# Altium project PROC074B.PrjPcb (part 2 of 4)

## Sheet PROC074B_LP_Connector.SchDoc
size 431 x 279 mm; Date: Not shown in title block; ApprovedBy: Not shown in title block; CheckedBy: Not shown in title block; Author: Not shown in title block; CompanyName: Not shown in title block; Engineer: Not shown in title block; Organization: Not shown in title block; Address1: Not shown in title block; Address2: Not shown in title block; Address3: Not shown in title block; Address4: Not shown in title block; DocumentNumber: 1; Revision: Use project parameter SCH_Rev; SheetNumber: 8; SheetTotal: 22; PageSetup: Record=PageOptions¦CenterHorizontal=True¦CenterVertical=True¦PrintScale=1.00¦XCorrection=1.00¦YCorrection=1.00¦PrintKind=0¦BorderSize=5000000¦LeftOffset=0¦BottomOffset=0¦Orientation=2¦PaperLength=1000¦PaperWidth=1000¦Scale=100¦PaperSource=15¦PrintQuality=600¦MediaType=1¦DitherType=10¦PaperKind=Letter¦PrintScaleMode=1
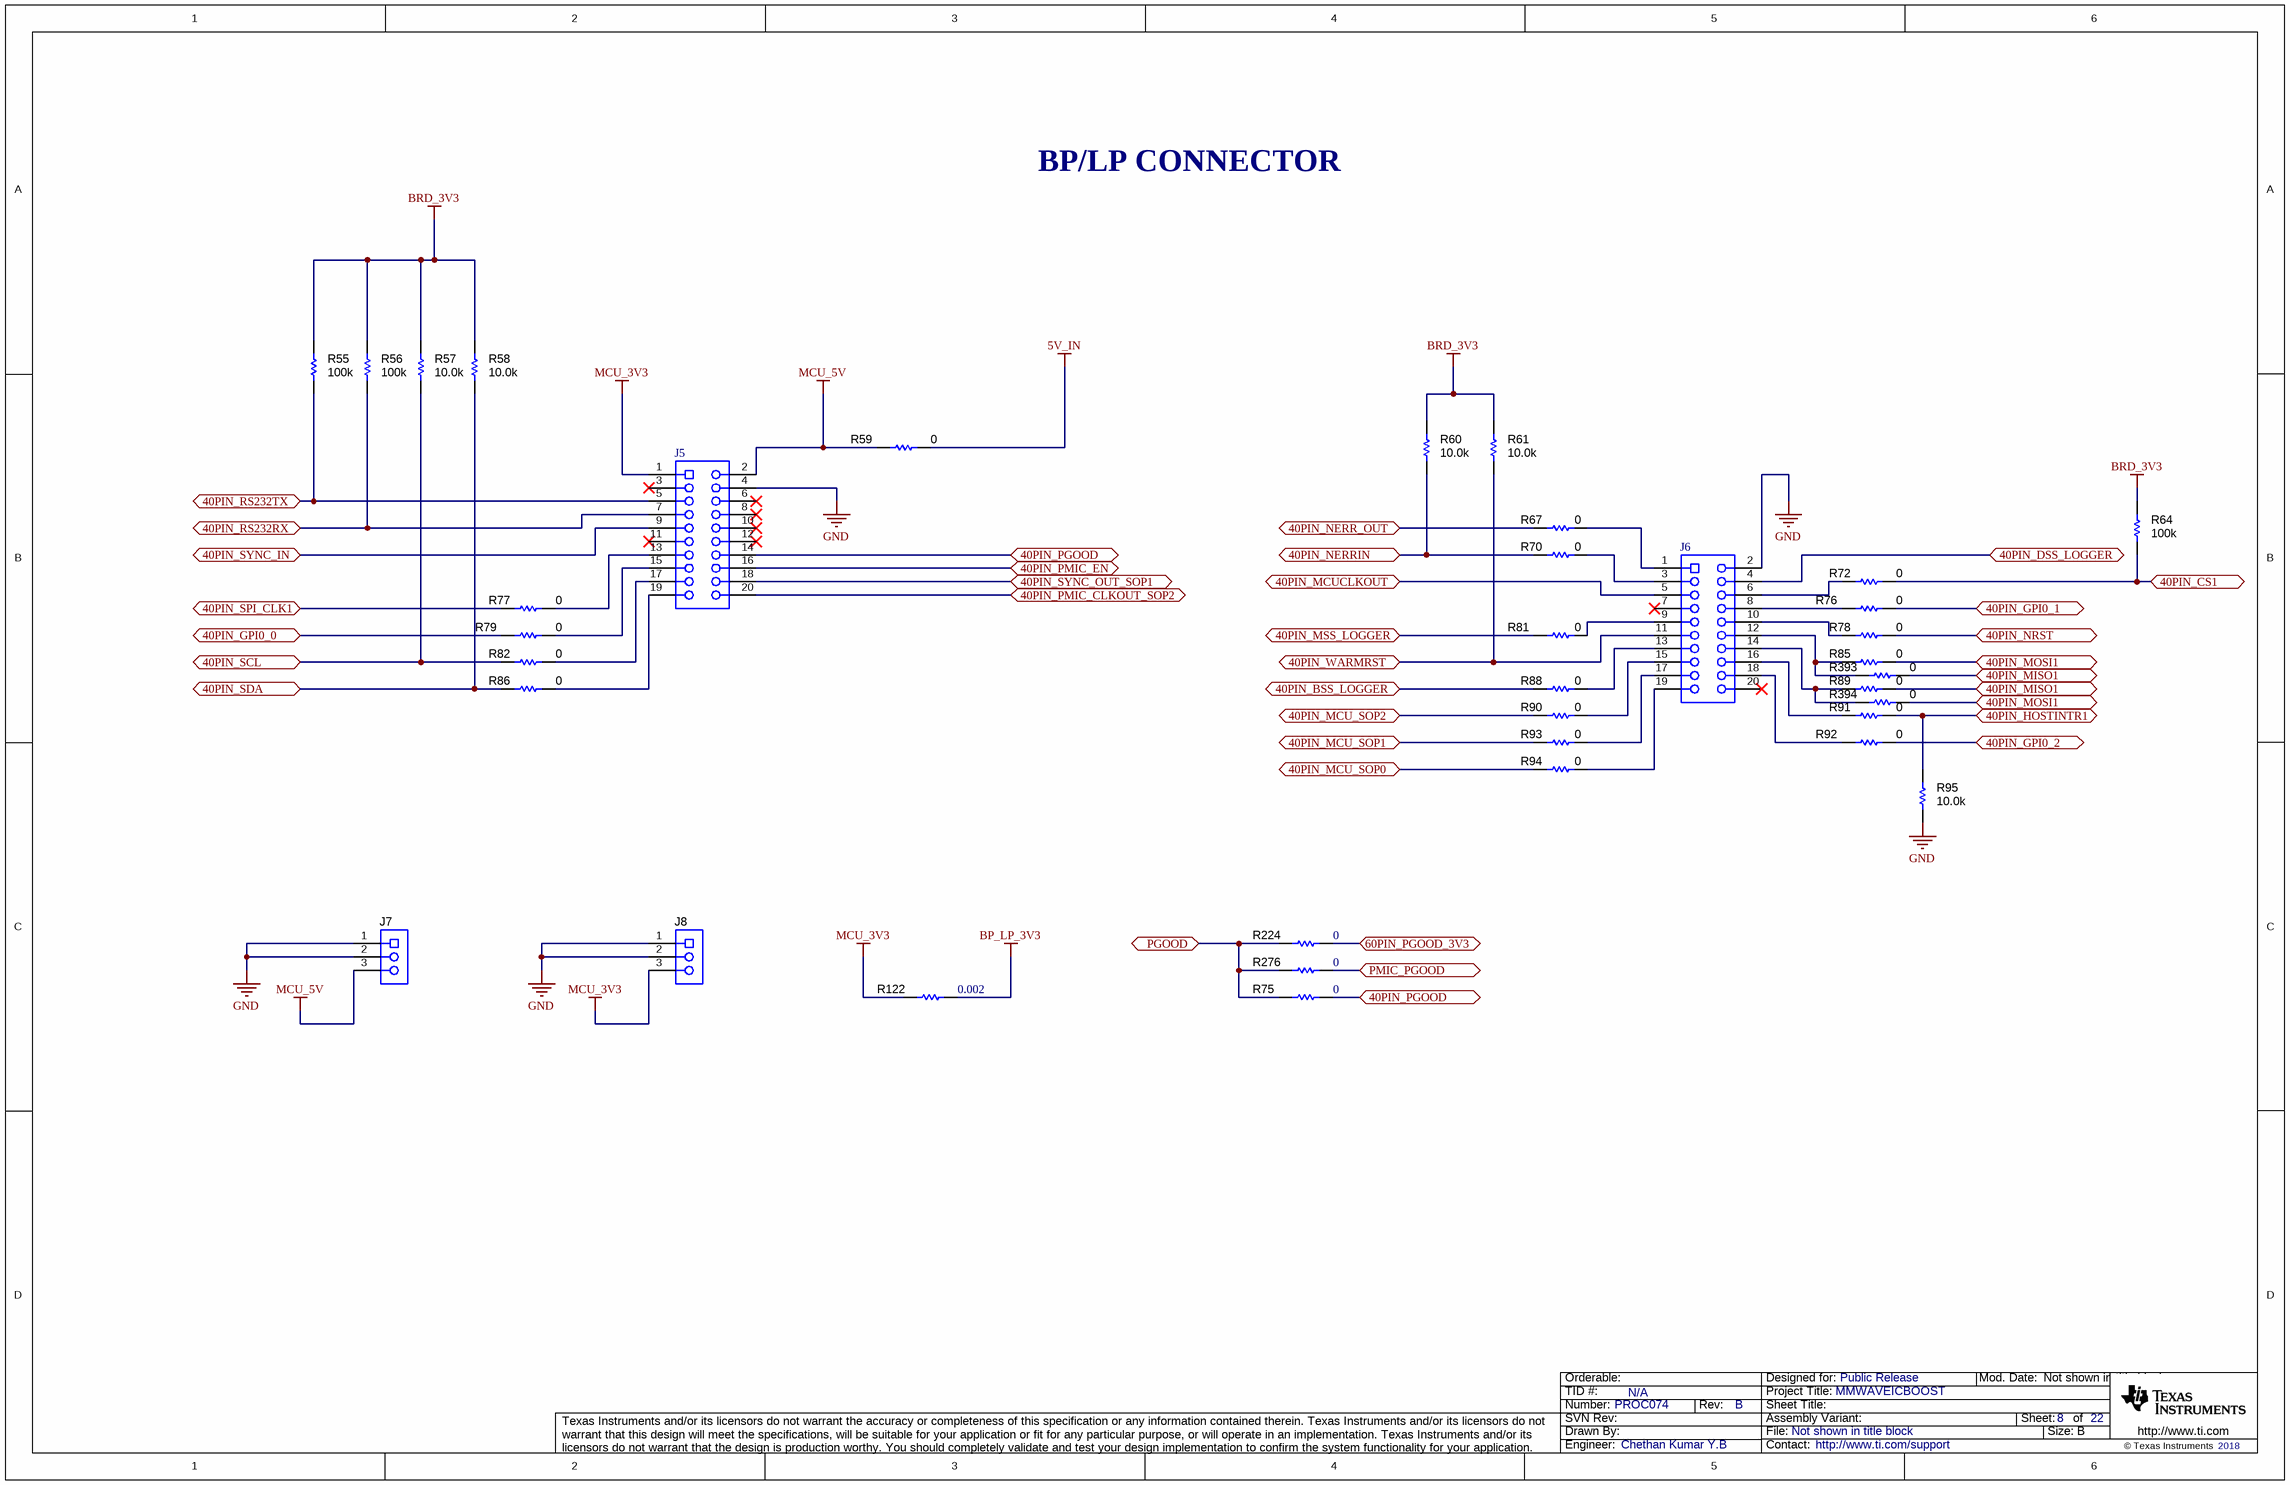
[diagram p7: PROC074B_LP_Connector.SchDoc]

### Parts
J5  SSM-110-S-DV  [Samtec_SSM-110-x-DV]  (value not drawn)
J6  SSM-110-S-DV  [Samtec_SSM-110-x-DV]  (value not drawn)
J7  SSM-103-S-SV  [Samtec_SSM-103-x-SV]  (value not drawn)
J8  SSM-103-S-SV  [Samtec_SSM-103-x-SV]  (value not drawn)
R55  ValueDisplayed: 100k  [0402L]  (hidden comment: CRCW0402100KFKED)
R56  ValueDisplayed: 100k  [0402L]  (hidden comment: CRCW0402100KFKED)
R57  ValueDisplayed: 10.0k  [0402L]  (hidden comment: CRCW040210K0FKED)
R58  ValueDisplayed: 10.0k  [0402L]  (hidden comment: CRCW040210K0FKED)
R59  ValueDisplayed: 0  [2010]  (hidden comment: CRCW20100000Z0EF)
R60  ValueDisplayed: 10.0k  [0402L]  (hidden comment: CRCW040210K0FKED)
R61  ValueDisplayed: 10.0k  [0402L]  (hidden comment: CRCW040210K0FKED)
R64  ValueDisplayed: 100k  [0402L]  (hidden comment: CRCW0402100KFKED)
R67  ValueDisplayed: 0  [0201_Silk]  (hidden comment: CRCW02010000Z0ED)
R70  ValueDisplayed: 0  [0201_Silk]  (hidden comment: CRCW02010000Z0ED)
R72  ValueDisplayed: 0  [0201_Silk]  (hidden comment: CRCW02010000Z0ED)
R75  ValueDisplayed: 0  [0402]  (hidden comment: ERJ-2GE0R00X)
R76  ValueDisplayed: 0  [0201_Silk]  (hidden comment: CRCW02010000Z0ED)
R77  ValueDisplayed: 0  [0201_Silk]  (hidden comment: CRCW02010000Z0ED)
R78  ValueDisplayed: 0  [0201_Silk]  (hidden comment: CRCW02010000Z0ED)
R79  ValueDisplayed: 0  [0201_Silk]  (hidden comment: CRCW02010000Z0ED)
R81  ValueDisplayed: 0  [0201_Silk]  (hidden comment: CRCW02010000Z0ED)
R82  ValueDisplayed: 0  [0201_Silk]  (hidden comment: CRCW02010000Z0ED)
R85  ValueDisplayed: 0  [0201_Silk]  (hidden comment: CRCW02010000Z0ED)
R86  ValueDisplayed: 0  [0201_Silk]  (hidden comment: CRCW02010000Z0ED)
R88  ValueDisplayed: 0  [0201_Silk]  (hidden comment: CRCW02010000Z0ED)
R89  ValueDisplayed: 0  [0201_Silk]  (hidden comment: CRCW02010000Z0ED)
R90  ValueDisplayed: 0  [0201_Silk]  (hidden comment: CRCW02010000Z0ED)
R91  ValueDisplayed: 0  [0201_Silk]  (hidden comment: CRCW02010000Z0ED)
R92  ValueDisplayed: 0  [0201_Silk]  (hidden comment: CRCW02010000Z0ED)
R93  ValueDisplayed: 0  [0201_Silk]  (hidden comment: CRCW02010000Z0ED)
R94  ValueDisplayed: 0  [0201_Silk]  (hidden comment: CRCW02010000Z0ED)
R95  ValueDisplayed: 10.0k  [0402L]  (hidden comment: CRCW040210K0FKED)
R122  ValueDisplayed: 0.002  [1206]  (hidden comment: PMR18EZPFV2L00)
R224  ValueDisplayed: 0  [0402]  (hidden comment: ERJ-2GE0R00X)
R276  ValueDisplayed: 0  [0402]  (hidden comment: ERJ-2GE0R00X)
R393  ValueDisplayed: 0  [0201_Silk]  (hidden comment: CRCW02010000Z0ED)
R394  ValueDisplayed: 0  [0201_Silk]  (hidden comment: CRCW02010000Z0ED)

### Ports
40PIN_BSS_LOGGER, 40PIN_CS1, 40PIN_DSS_LOGGER, 40PIN_GPI0_0, 40PIN_GPI0_1, 40PIN_GPI0_2, 40PIN_HOSTINTR1, 40PIN_MCU_SOP0, 40PIN_MCU_SOP1, 40PIN_MCU_SOP2, 40PIN_MCUCLKOUT, 40PIN_MISO1, 40PIN_MOSI1, 40PIN_MSS_LOGGER, 40PIN_NERR_OUT, 40PIN_NERRIN, 40PIN_NRST, 40PIN_PGOOD, 40PIN_PMIC_CLKOUT_SOP2, 40PIN_PMIC_EN, 40PIN_RS232RX, 40PIN_RS232TX, 40PIN_SCL, 40PIN_SDA, 40PIN_SPI_CLK1, 40PIN_SYNC_IN, 40PIN_SYNC_OUT_SOP1, 40PIN_WARMRST, 60PIN_PGOOD_3V3, PGOOD, PMIC_PGOOD

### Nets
5V_IN: R59.2
BP_LP_3V3: R122.2
BRD_3V3: R55.2 R56.2 R57.2 R58.2 R60.2 R61.2 R64.2
GND: J5.4 J6.2 J7.1 J7.2 J8.1 J8.2 R95.1
MCU_3V3: J5.1 J8.3 R122.1
MCU_5V: J5.2 J7.3 R59.1
40PIN_BSS_LOGGER: R88.1 ; port 40PIN_BSS_LOGGER
40PIN_CS1: R64.1 R72.2 ; port 40PIN_CS1
40PIN_DSS_LOGGER: J6.4 ; port 40PIN_DSS_LOGGER
40PIN_GPI0_0: R79.1 ; port 40PIN_GPI0_0
40PIN_GPI0_1: R76.2 ; port 40PIN_GPI0_1
40PIN_GPI0_2: R92.2 ; port 40PIN_GPI0_2
40PIN_HOSTINTR1: R91.2 R95.2 ; port 40PIN_HOSTINTR1
40PIN_MCU_SOP0: R94.1 ; port 40PIN_MCU_SOP0
40PIN_MCU_SOP1: R93.1 ; port 40PIN_MCU_SOP1
40PIN_MCU_SOP2: R90.1 ; port 40PIN_MCU_SOP2
40PIN_MCUCLKOUT: J6.5 ; port 40PIN_MCUCLKOUT
40PIN_MISO1: R89.2 R393.2 ; port 40PIN_MISO1
40PIN_MOSI1: R85.2 R394.2 ; port 40PIN_MOSI1
40PIN_MSS_LOGGER: R81.1 ; port 40PIN_MSS_LOGGER
40PIN_NERR_OUT: R67.1 ; port 40PIN_NERR_OUT
40PIN_NERRIN: R60.1 R70.1 ; port 40PIN_NERRIN
40PIN_NRST: R78.2 ; port 40PIN_NRST
40PIN_PGOOD: J5.14 R75.2 ; port 40PIN_PGOOD
40PIN_PMIC_CLKOUT_SOP2: J5.20 ; port 40PIN_PMIC_CLKOUT_SOP2
40PIN_PMIC_EN: J5.16 ; port 40PIN_PMIC_EN
40PIN_RS232RX: J5.7 R56.1 ; port 40PIN_RS232RX
40PIN_RS232TX: J5.5 R55.1 ; port 40PIN_RS232TX
40PIN_SCL: R57.1 R82.1 ; port 40PIN_SCL
40PIN_SDA: R58.1 R86.1 ; port 40PIN_SDA
40PIN_SPI_CLK1: R77.1 ; port 40PIN_SPI_CLK1
40PIN_SYNC_IN: J5.9 ; port 40PIN_SYNC_IN
40PIN_SYNC_OUT_SOP1: J5.18 ; port 40PIN_SYNC_OUT_SOP1
40PIN_WARMRST: J6.11 R61.1 ; port 40PIN_WARMRST
60PIN_PGOOD_3V3: R224.2 ; port 60PIN_PGOOD_3V3
PGOOD: R75.1 R224.1 R276.1 ; port PGOOD
PMIC_PGOOD: R276.2 ; port PMIC_PGOOD
NetJ5_13: J5.13 R77.2
NetJ5_15: J5.15 R79.2
NetJ5_17: J5.17 R82.2
NetJ5_19: J5.19 R86.2
NetJ6_1: J6.1 R67.2
NetJ6_3: J6.3 R70.2
NetJ6_6: J6.6 R72.1
NetJ6_8: J6.8 R76.1
NetJ6_9: J6.9 R81.2
NetJ6_10: J6.10 R78.1
NetJ6_12: J6.12 R85.1 R393.1
NetJ6_13: J6.13 R88.2
NetJ6_14: J6.14 R89.1 R394.1
NetJ6_15: J6.15 R90.2
NetJ6_16: J6.16 R91.1
NetJ6_17: J6.17 R93.2
NetJ6_18: J6.18 R92.1
NetJ6_19: J6.19 R94.2

Not connected (* = marked no-connect by the designer): J5 3* 6* 8* 10* 11* 12*; J6 7* 20*

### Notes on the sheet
- BP/LP CONNECTOR

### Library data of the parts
J5 J6 = CMP-0078182-1: Receptacle, 2.54mm, 10x2, Gold with Tin tail, SMT; Manufacturer: Samtec; Pitch_mm: 2.54; Gender: Female; Cert_CSA: Y; Voltage_V: 405V; Current_A: 5.2A; Row_Count: 2; CompType: Socket Strip
J7 J8 = CMP-0078183-1: Receptacle, 2.54mm, 3x1, Gold with Tin tail, SMT; Manufacturer: Samtec; Pitch_mm: 2.54; Gender: Female; Cert_CSA: Y; Voltage_V: 405V; Current_A: 5.2A; Row_Count: 1; CompType: Socket Strip
R55 R56 R64 = CMP-0025950-2: RES, 100 k, 1%, 0.063 W, 0402; Manufacturer: Vishay-Dale; Power_W: 63mW; TempCo: 100 ppm/C; U/M: EA; Value: 100k; EIA_Code: E96; SizeX_mm: 1; SizeY_mm: 0.5; SizeZ_mm: 0.6; Value2: 0.063W; CompType: Resistor; VDC_V: 50V; AEC Category: Q200; INSTALLATION: DNP
R57 R58 R60 R61 R95 = CMP-0025958-2: RES, 10.0 k, 1%, 0.063 W, 0402; Manufacturer: Vishay-Dale; Power_W: 63mW; TempCo: 100 ppm/C; Value_Code: 10k0; U/M: EA; Value: 10.0k; EIA_Code: E96; Res_ohm: 10k; SizeX_mm: 1; SizeY_mm: 0.5; SizeZ_mm: 0.6; Value2: 0.063W; CompType: Resistor; VDC_V: 50V; AEC Category: Q200; INSTALLATION: DNP
R59 = CMP-0016044-2: RES, 0, 5%, 0.75 W, AEC-Q200 Grade 0, 2010; Manufacturer: Vishay-Dale; Power_W: 750mW; TempCo: ppm/C; Value_Code: 0000; U/M: EA; Value: 0; EIA_Code: E24; SizeX_mm: 5; SizeY_mm: 2.5; SizeZ_mm: 1.66; Value2: 0.75W; SizeArea_mm2: 12.5; CompType: Resistor; AEC Qualified: Y; AEC Category: Q200; INSTALLATION: DNP
R67 R70 R72 R88 R90 R93 R94 = CMP-0027008-3: RES, 0, 5%, 0.05 W, 0201; Manufacturer: Vishay-Dale; Power_W: 50mW; TempCo: ppm/C; Value_Code: 0000; U/M: EA; Value: 0; EIA_Code: E24; SizeX_mm: 0.6; SizeY_mm: 0.3; SizeZ_mm: 0.26; Value2: 0.05W; SizeArea_mm2: 0.18; CompType: Resistor; AEC Qualified: N; AEC Category: Q200
R75 R276 = CMP-0026992-3: RES, 0, 5%, 0.1 W, AEC-Q200 Grade 0, 0402; Manufacturer: Panasonic; Power_W: 100mW; TempCo: 600 ppm/C; Value_Code: 0000; Value: 0; EIA_Code: E24; SizeX_mm: 1; SizeY_mm: 0.5; SizeZ_mm: 0.6; Value2: 0.1W; CompType: Resistor; AEC Qualified: Y; VDC_V: 50V; AEC Category: Q200; SizeAreaWB_mm2: 3; INSTALLATION: DNP
R76 R79 R81 R92 R393 R394 = CMP-0027008-3: RES, 0, 5%, 0.05 W, 0201; Manufacturer: Vishay-Dale; Power_W: 50mW; TempCo: ppm/C; Value_Code: 0000; U/M: EA; Value: 0; EIA_Code: E24; SizeX_mm: 0.6; SizeY_mm: 0.3; SizeZ_mm: 0.26; Value2: 0.05W; SizeArea_mm2: 0.18; CompType: Resistor; AEC Qualified: N; AEC Category: Q200; INSTALLATION: DNP
R77 R78 R82 R85 R86 R89 R91 = CMP-0027008-3: RES, 0, 5%, 0.05 W, 0201; Manufacturer: Vishay-Dale; Power_W: 50mW; TempCo: ppm/C; Value_Code: 0000; U/M: EA; Value: 0; EIA_Code: E24; SizeX_mm: 0.6; SizeY_mm: 0.3; SizeZ_mm: 0.26; Value2: 0.05W; SizeArea_mm2: 0.18; AEC Qualified: N; AEC Category: Q200
R122 = CMP-0081623-1: RES, 0.002, 1%, 1 W, AEC-Q200 Grade 0, 1206; Manufacturer: Rohm; Value_Code: 2L000; SizeAreaWB_mm2: 10.92; SizeArea_mm2: 5.12; AEC Qualified: Y; AEC Category: Q200; Res_ohm: 2m; Value: 0.002; SizeZ_mm: 1.35; Green_REACh: Incomplete; TempCo: 100 ppm/C; AEC Grade: 0; Power_W: 1W; SizeY_mm: 1.6; Green_Lifecycle: Active; CompType: Resistor; SizeX_mm: 3.2; INSTALLATION: DNP
R224 = CMP-0026992-3: RES, 0, 5%, 0.1 W, AEC-Q200 Grade 0, 0402; Manufacturer: Panasonic; Power_W: 100mW; TempCo: 600 ppm/C; Value_Code: 0000; Value: 0; EIA_Code: E24; SizeX_mm: 1; SizeY_mm: 0.5; SizeZ_mm: 0.6; Value2: 0.1W; AEC Qualified: Y; VDC_V: 50V; AEC Category: Q200; SizeAreaWB_mm2: 3

## Sheet PROC074B_BP_LP_RNR_Options.SchDoc
size 431 x 279 mm; Date: Not shown in title block; ApprovedBy: Not shown in title block; CheckedBy: Not shown in title block; Author: Not shown in title block; CompanyName: Not shown in title block; Engineer: Not shown in title block; Organization: Not shown in title block; Address1: Not shown in title block; Address2: Not shown in title block; Address3: Not shown in title block; Address4: Not shown in title block; DocumentNumber: 1; Revision: Use project parameter SCH_Rev; SheetNumber: 9; SheetTotal: 22; PageSetup: Record=PageOptions¦CenterHorizontal=True¦CenterVertical=True¦PrintScale=1.00¦XCorrection=1.00¦YCorrection=1.00¦PrintKind=0¦BorderSize=5000000¦LeftOffset=0¦BottomOffset=0¦Orientation=2¦PaperLength=1000¦PaperWidth=1000¦Scale=100¦PaperSource=15¦PrintQuality=600¦MediaType=1¦DitherType=10¦PaperKind=Letter¦PrintScaleMode=1
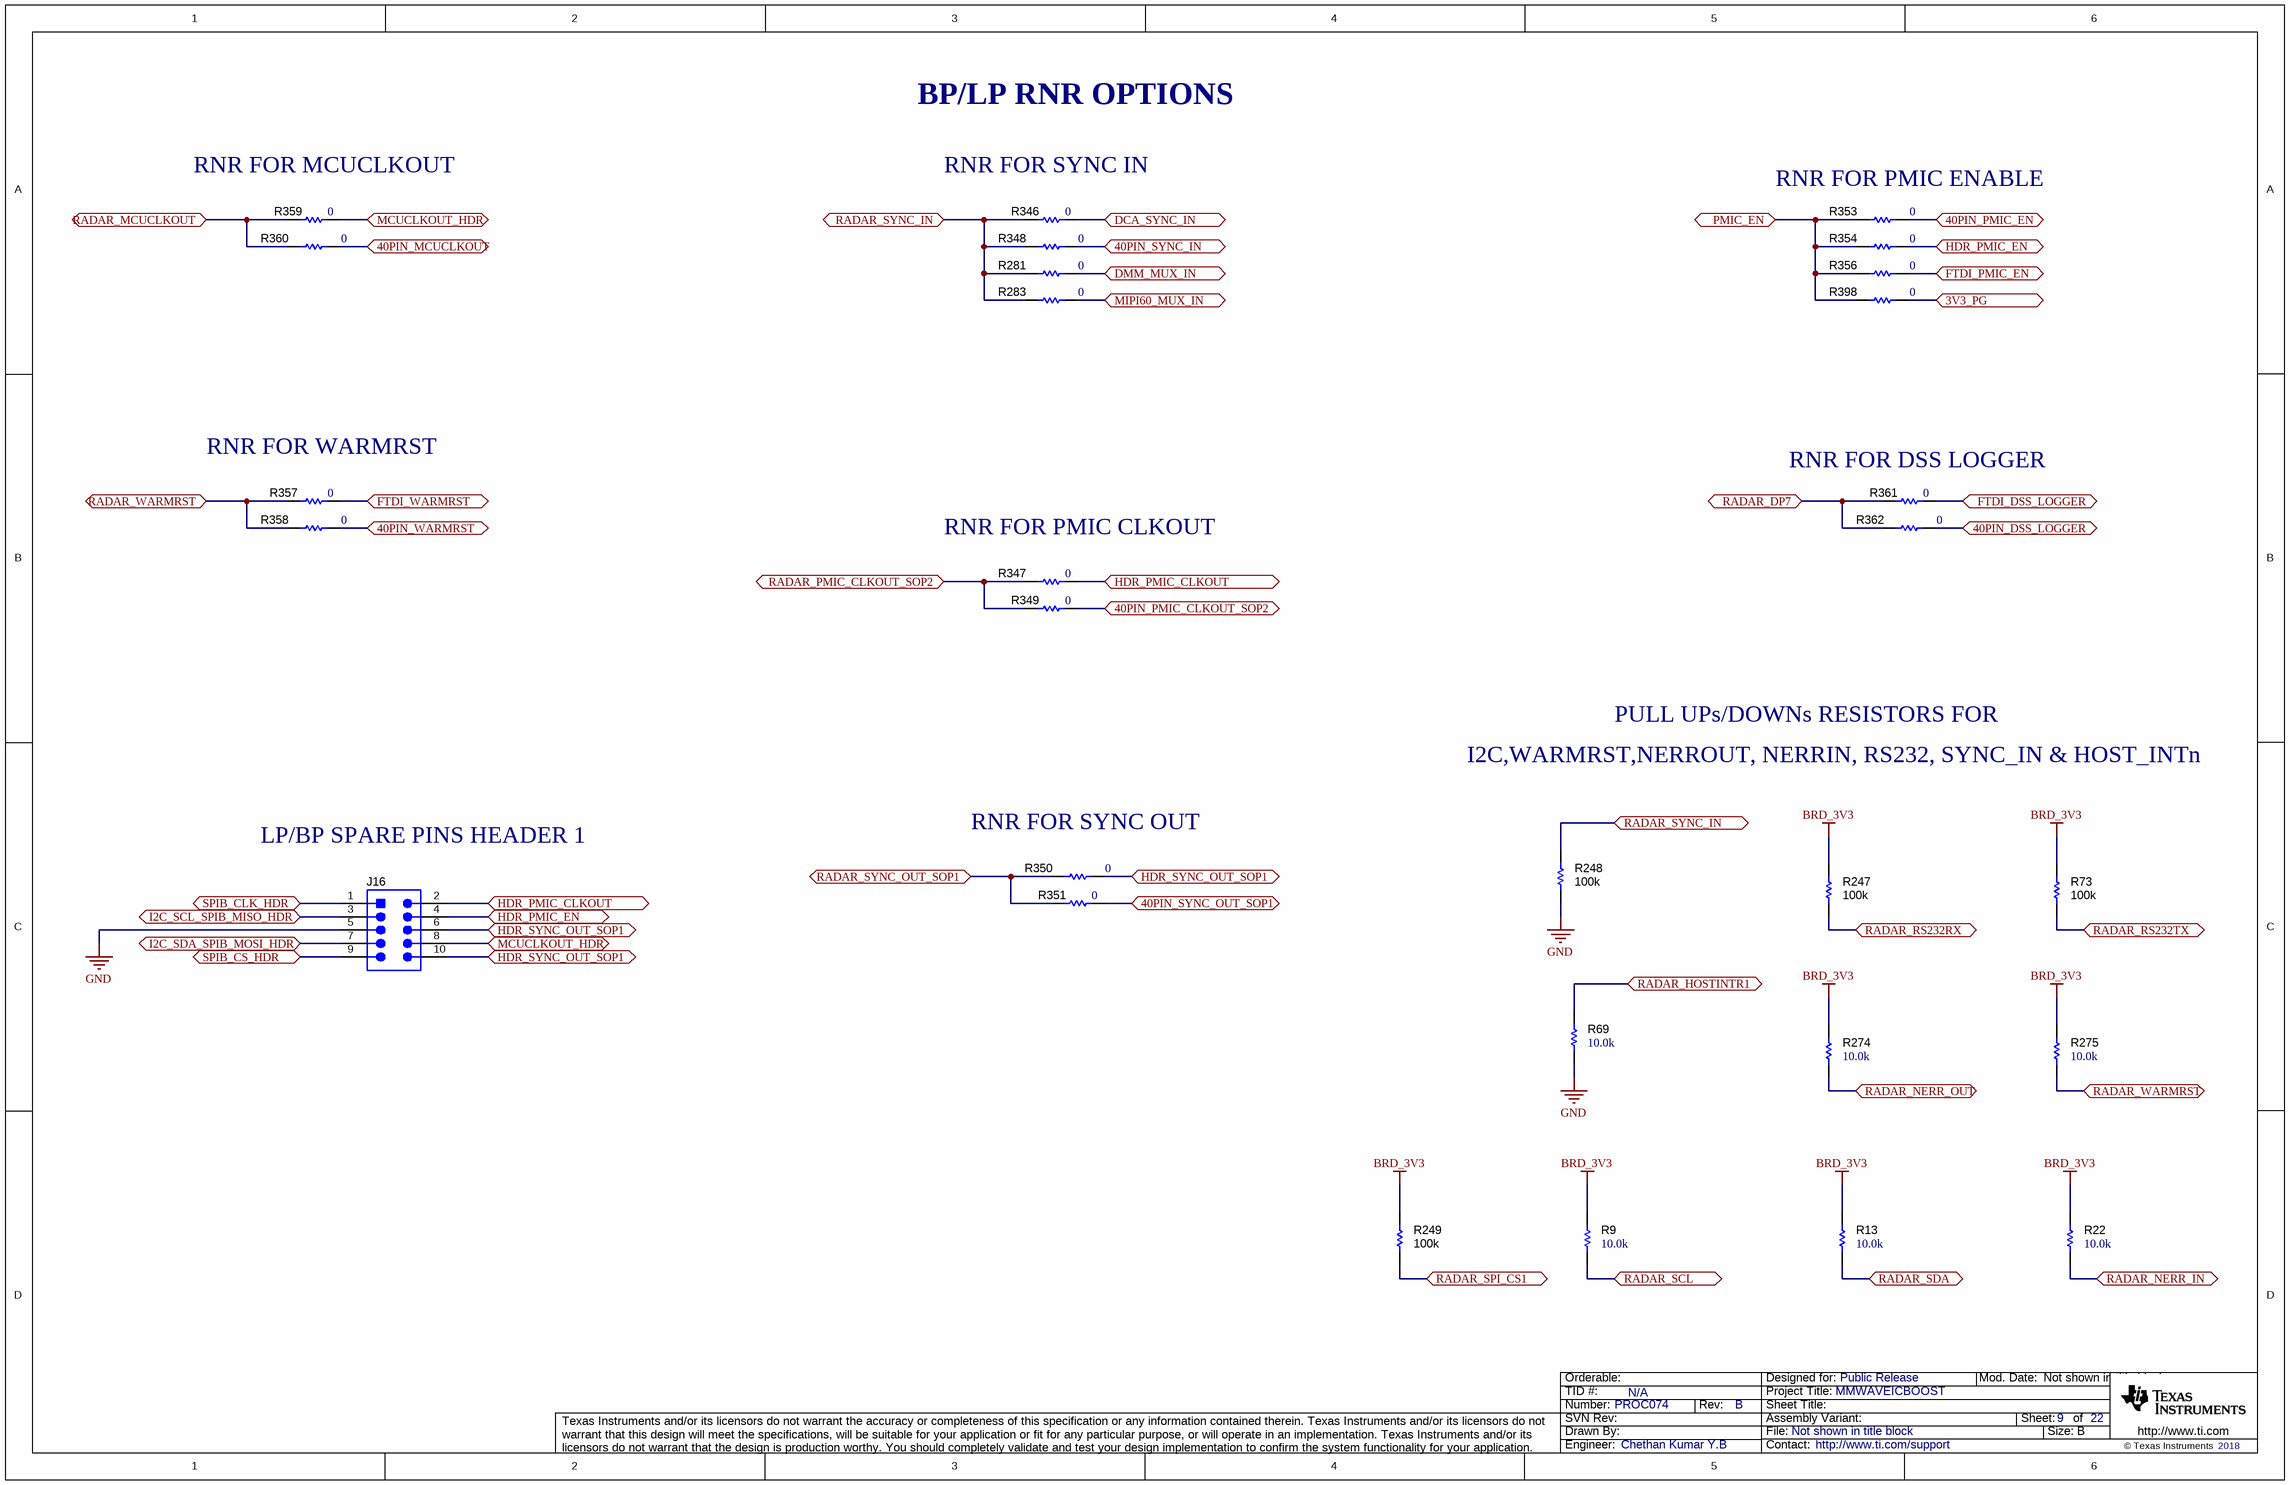
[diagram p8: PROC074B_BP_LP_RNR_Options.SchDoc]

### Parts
J16  TSW-105-07-G-D  [TSW-105-07-G-D]  (value not drawn)
R9  ValueDisplayed: 10.0k  [0402]  (hidden comment: CRCW040210K0FKED)
R13  ValueDisplayed: 10.0k  [0402]  (hidden comment: CRCW040210K0FKED)
R22  ValueDisplayed: 10.0k  [0402]  (hidden comment: CRCW040210K0FKED)
R69  ValueDisplayed: 10.0k  [0402]  (hidden comment: CRCW040210K0FKED)
R73  ValueDisplayed: 100k  [0402L]  (hidden comment: CRCW0402100KFKED)
R247  ValueDisplayed: 100k  [0402L]  (hidden comment: CRCW0402100KFKED)
R248  ValueDisplayed: 100k  [0402L]  (hidden comment: CRCW0402100KFKED)
R249  ValueDisplayed: 100k  [0402L]  (hidden comment: CRCW0402100KFKED)
R274  ValueDisplayed: 10.0k  [0402]  (hidden comment: CRCW040210K0FKED)
R275  ValueDisplayed: 10.0k  [0402]  (hidden comment: CRCW040210K0FKED)
R281  ValueDisplayed: 0  [0402]  (hidden comment: ERJ-2GE0R00X)
R283  ValueDisplayed: 0  [0402]  (hidden comment: ERJ-2GE0R00X)
R346  ValueDisplayed: 0  [0402]  (hidden comment: ERJ-2GE0R00X)
R347  ValueDisplayed: 0  [0402]  (hidden comment: ERJ-2GE0R00X)
R348  ValueDisplayed: 0  [0402]  (hidden comment: ERJ-2GE0R00X)
R349  ValueDisplayed: 0  [0402]  (hidden comment: ERJ-2GE0R00X)
R350  ValueDisplayed: 0  [0402]  (hidden comment: ERJ-2GE0R00X)
R351  ValueDisplayed: 0  [0402]  (hidden comment: ERJ-2GE0R00X)
R353  ValueDisplayed: 0  [0402]  (hidden comment: ERJ-2GE0R00X)
R354  ValueDisplayed: 0  [0402]  (hidden comment: ERJ-2GE0R00X)
R356  ValueDisplayed: 0  [0402]  (hidden comment: ERJ-2GE0R00X)
R357  ValueDisplayed: 0  [0402]  (hidden comment: ERJ-2GE0R00X)
R358  ValueDisplayed: 0  [0402]  (hidden comment: ERJ-2GE0R00X)
R359  ValueDisplayed: 0  [0402]  (hidden comment: ERJ-2GE0R00X)
R360  ValueDisplayed: 0  [0402]  (hidden comment: ERJ-2GE0R00X)
R361  ValueDisplayed: 0  [0402]  (hidden comment: ERJ-2GE0R00X)
R362  ValueDisplayed: 0  [0402]  (hidden comment: ERJ-2GE0R00X)
R398  ValueDisplayed: 0  [0402]  (hidden comment: ERJ-2GE0R00X)

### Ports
3V3_PG, 40PIN_DSS_LOGGER, 40PIN_MCUCLKOUT, 40PIN_PMIC_CLKOUT_SOP2, 40PIN_PMIC_EN, 40PIN_SYNC_IN, 40PIN_SYNC_OUT_SOP1, 40PIN_WARMRST, DCA_SYNC_IN, DMM_MUX_IN, FTDI_DSS_LOGGER, FTDI_PMIC_EN, FTDI_WARMRST, HDR_PMIC_CLKOUT, HDR_PMIC_EN, HDR_SYNC_OUT_SOP1, I2C_SCL_SPIB_MISO_HDR, I2C_SDA_SPIB_MOSI_HDR, MCUCLKOUT_HDR, MIPI60_MUX_IN, PMIC_EN, RADAR_DP7, RADAR_HOSTINTR1, RADAR_MCUCLKOUT, RADAR_NERR_IN, RADAR_NERR_OUT, RADAR_PMIC_CLKOUT_SOP2, RADAR_RS232RX, RADAR_RS232TX, RADAR_SCL, RADAR_SDA, RADAR_SPI_CS1, RADAR_SYNC_IN, RADAR_SYNC_OUT_SOP1, RADAR_WARMRST, SPIB_CLK_HDR, SPIB_CS_HDR

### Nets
BRD_3V3: R9.2 R13.2 R22.2 R73.2 R247.2 R249.2 R274.2 R275.2
GND: J16.5 R69.1 R248.1
3V3_PG: R398.2 ; port 3V3_PG
40PIN_DSS_LOGGER: R362.2 ; port 40PIN_DSS_LOGGER
40PIN_MCUCLKOUT: R360.2 ; port 40PIN_MCUCLKOUT
40PIN_PMIC_CLKOUT_SOP2: R349.2 ; port 40PIN_PMIC_CLKOUT_SOP2
40PIN_PMIC_EN: R353.2 ; port 40PIN_PMIC_EN
40PIN_SYNC_IN: R348.2 ; port 40PIN_SYNC_IN
40PIN_SYNC_OUT_SOP1: R351.2 ; port 40PIN_SYNC_OUT_SOP1
40PIN_WARMRST: R358.2 ; port 40PIN_WARMRST
DCA_SYNC_IN: R346.2 ; port DCA_SYNC_IN
DMM_MUX_IN: R281.2 ; port DMM_MUX_IN
FTDI_DSS_LOGGER: R361.2 ; port FTDI_DSS_LOGGER
FTDI_PMIC_EN: R356.2 ; port FTDI_PMIC_EN
FTDI_WARMRST: R357.2 ; port FTDI_WARMRST
HDR_PMIC_CLKOUT: J16.2 R347.2 ; port HDR_PMIC_CLKOUT
HDR_PMIC_EN: J16.4 R354.2 ; port HDR_PMIC_EN
HDR_SYNC_OUT_SOP1: J16.6 J16.10 R350.2 ; port HDR_SYNC_OUT_SOP1
I2C_SCL_SPIB_MISO_HDR: J16.3 ; port I2C_SCL_SPIB_MISO_HDR
I2C_SDA_SPIB_MOSI_HDR: J16.7 ; port I2C_SDA_SPIB_MOSI_HDR
MCUCLKOUT_HDR: J16.8 R359.2 ; port MCUCLKOUT_HDR
MIPI60_MUX_IN: R283.2 ; port MIPI60_MUX_IN
PMIC_EN: R353.1 R354.1 R356.1 R398.1 ; port PMIC_EN
RADAR_DP7: R361.1 R362.1 ; port RADAR_DP7
RADAR_HOSTINTR1: R69.2 ; port RADAR_HOSTINTR1
RADAR_MCUCLKOUT: R359.1 R360.1 ; port RADAR_MCUCLKOUT
RADAR_NERR_IN: R22.1 ; port RADAR_NERR_IN
RADAR_NERR_OUT: R274.1 ; port RADAR_NERR_OUT
RADAR_PMIC_CLKOUT_SOP2: R347.1 R349.1 ; port RADAR_PMIC_CLKOUT_SOP2
RADAR_RS232RX: R247.1 ; port RADAR_RS232RX
RADAR_RS232TX: R73.1 ; port RADAR_RS232TX
RADAR_SCL: R9.1 ; port RADAR_SCL
RADAR_SDA: R13.1 ; port RADAR_SDA
RADAR_SPI_CS1: R249.1 ; port RADAR_SPI_CS1
RADAR_SYNC_IN: R248.2 R281.1 R283.1 R346.1 R348.1 ; port RADAR_SYNC_IN
RADAR_SYNC_OUT_SOP1: R350.1 R351.1 ; port RADAR_SYNC_OUT_SOP1
RADAR_WARMRST: R275.1 R357.1 R358.1 ; port RADAR_WARMRST
SPIB_CLK_HDR: J16.1 ; port SPIB_CLK_HDR
SPIB_CS_HDR: J16.9 ; port SPIB_CS_HDR

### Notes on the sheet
- BP/LP RNR OPTIONS
- (near R359) RNR FOR MCUCLKOUT
- (near R346) RNR FOR SYNC IN
- (near R353) RNR FOR PMIC ENABLE
- (near R357) RNR FOR WARMRST
- (near R361) RNR FOR DSS LOGGER
- (near R347) RNR FOR PMIC CLKOUT
- I2C,WARMRST,NERROUT, NERRIN, RS232, SYNC_IN & HOST_INTn
- PULL UPs/DOWNs RESISTORS FOR
- (near R350) RNR FOR SYNC OUT
- LP/BP SPARE PINS HEADER 1

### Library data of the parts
J16 = CMP-0075410-2: Header, 100mil, 5x2, Gold, TH; Manufacturer: Samtec; Pitch_mm: 2.54; Cert_VDE: N; Gender: Male; Cert_CSA: Y; Voltage_V: 550V; Green_REACh: Passed; Current_A: 6.3A; Green_Lifecycle: Active; Row_Count: 2
R9 R13 R22 R69 R274 R275 = CMP-0025958-3: RES, 10.0 k, 1%, 0.063 W, AEC-Q200 Grade 0, 0402; Manufacturer: Vishay-Dale; Power_W: 63mW; TempCo: 100 ppm/C; Value_Code: 10k0; Value: 10.0k; EIA_Code: E96; Res_ohm: 10k; SizeX_mm: 1; SizeY_mm: 0.5; SizeZ_mm: 0.6; Value2: 0.063W; CompType: Resistor; AEC Qualified: Y; VDC_V: 50V; AEC Category: Q200; AEC Grade: 0; INSTALLATION: DNP
R73 R247-R249 = CMP-0025950-2: as R55 on sheet PROC074B_LP_Connector
R281 R283 R347 R348 R350 R353 R354 R356 R358 R360 R362 = CMP-0026992-3: as R75 on sheet PROC074B_LP_Connector
R346 R349 R351 R357 R359 R361 R398 = CMP-0026992-3: as R224 on sheet PROC074B_LP_Connector

## Sheet PROC074B_HD_Conn_JTAG_HDR.SchDoc
size 431 x 279 mm; Date: Not shown in title block; ApprovedBy: Not shown in title block; CheckedBy: Not shown in title block; Author: Not shown in title block; CompanyName: Not shown in title block; Engineer: Not shown in title block; Organization: Not shown in title block; Address1: Not shown in title block; Address2: Not shown in title block; Address3: Not shown in title block; Address4: Not shown in title block; DocumentNumber: 1; Revision: Use project parameter SCH_Rev; SheetNumber: 10; SheetTotal: 22; PageSetup: Record=PageOptions¦CenterHorizontal=True¦CenterVertical=True¦PrintScale=1.00¦XCorrection=1.00¦YCorrection=1.00¦PrintKind=0¦BorderSize=5000000¦LeftOffset=0¦BottomOffset=0¦Orientation=2¦PaperLength=1000¦PaperWidth=1000¦Scale=100¦PaperSource=15¦PrintQuality=600¦MediaType=1¦DitherType=10¦PaperKind=Letter¦PrintScaleMode=1
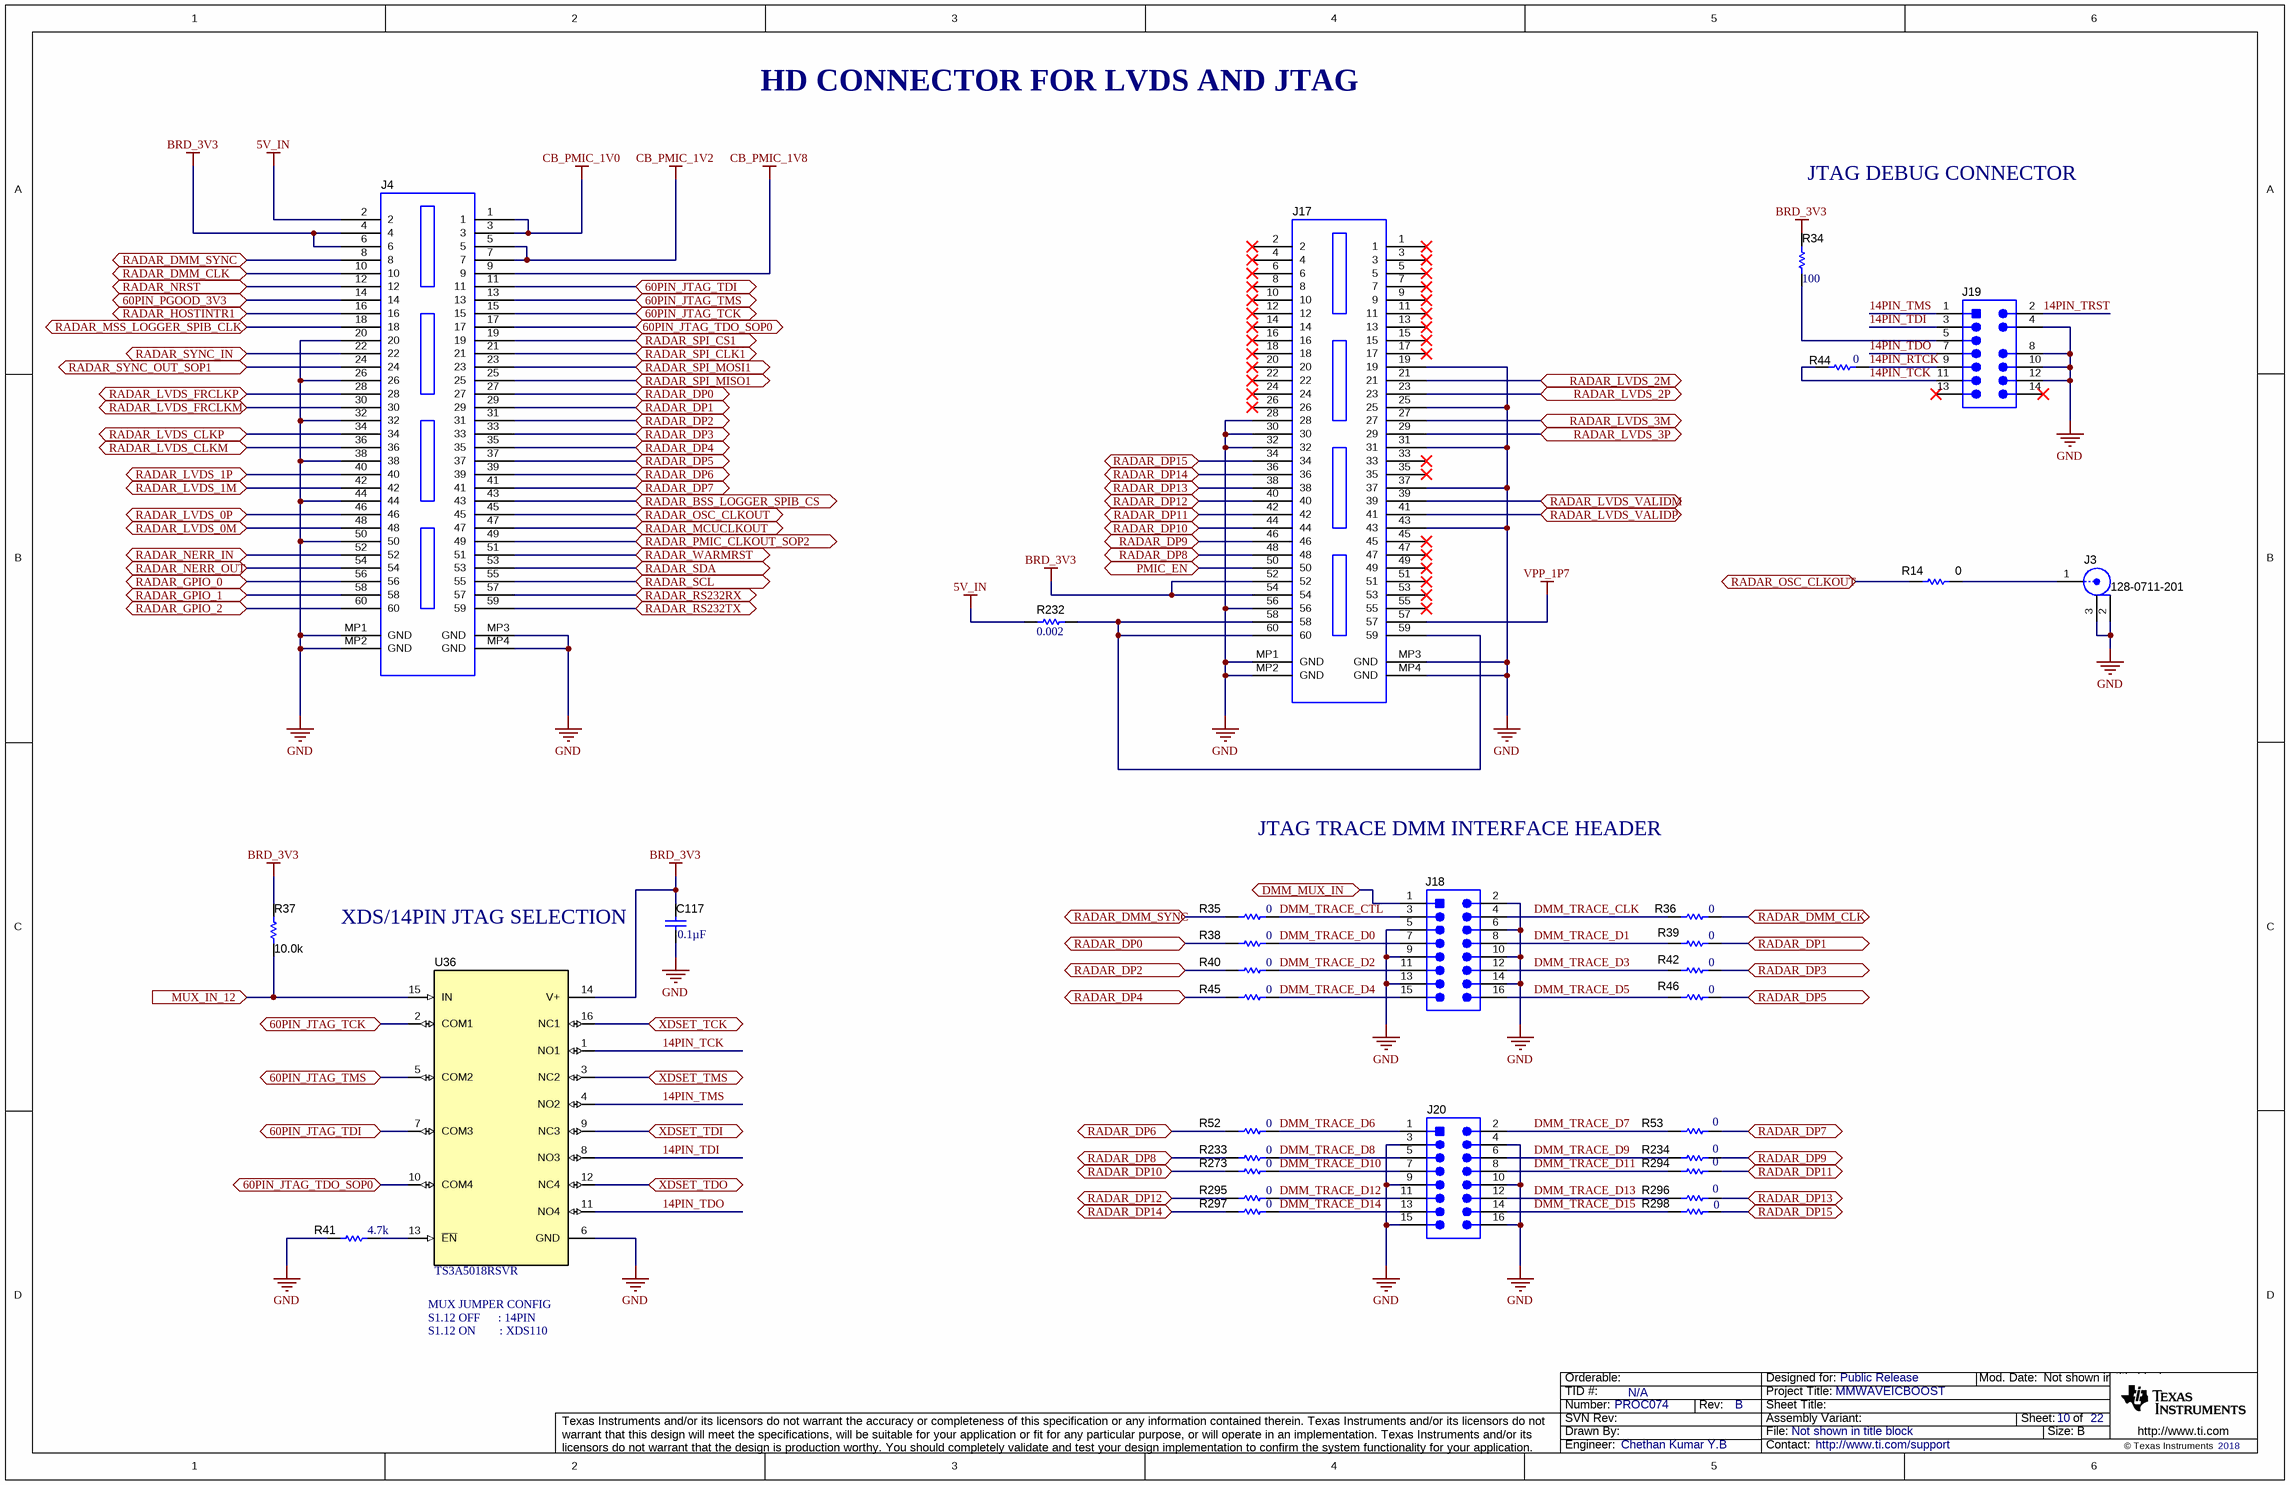
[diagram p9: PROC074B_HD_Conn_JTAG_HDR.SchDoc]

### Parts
C117  ValueDisplayed: 0.1µF  [0402]  (hidden comment: C0402C104K8RACTU)
J3  128-0711-201  [Johnson_128-0711-201]
J4  QTH-030-01-L-D-A  [Samtec_QTH-030-01-x-D-A]  (value not drawn)
J17  QTH-030-01-L-D-A  [Samtec_QTH-030-01-x-D-A]  (value not drawn)
J18  TSW-108-07-G-D  [TSW-108-07-G-D]  (value not drawn)
J19  TSW-107-07-L-D-006  [Samtec_TSW-107-07-L-D-006]  (value not drawn)
J20  TSW-108-07-G-D  [TSW-108-07-G-D]  (value not drawn)
R14  ValueDisplayed: 0  [0201_Silk]  (hidden comment: CRCW02010000Z0ED)
R34  ValueDisplayed: 100  [0402]  (hidden comment: ERJ-2GEJ101X)
R35  ValueDisplayed: 0  [0402]  (hidden comment: ERJ-2GE0R00X)
R36  ValueDisplayed: 0  [0402]  (hidden comment: ERJ-2GE0R00X)
R37  ValueDisplayed: 10.0k  [0402L]  (hidden comment: CRCW040210K0FKED)
R38  ValueDisplayed: 0  [0402]  (hidden comment: ERJ-2GE0R00X)
R39  ValueDisplayed: 0  [0402]  (hidden comment: ERJ-2GE0R00X)
R40  ValueDisplayed: 0  [0402]  (hidden comment: ERJ-2GE0R00X)
R41  ValueDisplayed: 4.7k  [0402]  (hidden comment: CRCW04024K70JNED)
R42  ValueDisplayed: 0  [0402]  (hidden comment: ERJ-2GE0R00X)
R44  ValueDisplayed: 0  [0402]  (hidden comment: ERJ-2GE0R00X)
R45  ValueDisplayed: 0  [0402]  (hidden comment: ERJ-2GE0R00X)
R46  ValueDisplayed: 0  [0402]  (hidden comment: ERJ-2GE0R00X)
R52  ValueDisplayed: 0  [0402]  (hidden comment: ERJ-2GE0R00X)
R53  ValueDisplayed: 0  [0402]  (hidden comment: ERJ-2GE0R00X)
R232  ValueDisplayed: 0.002  [1206]  (hidden comment: PMR18EZPFV2L00)
R233  ValueDisplayed: 0  [0402]  (hidden comment: ERJ-2GE0R00X)
R234  ValueDisplayed: 0  [0402]  (hidden comment: ERJ-2GE0R00X)
R273  ValueDisplayed: 0  [0402]  (hidden comment: ERJ-2GE0R00X)
R294  ValueDisplayed: 0  [0402]  (hidden comment: ERJ-2GE0R00X)
R295  ValueDisplayed: 0  [0402]  (hidden comment: ERJ-2GE0R00X)
R296  ValueDisplayed: 0  [0402]  (hidden comment: ERJ-2GE0R00X)
R297  ValueDisplayed: 0  [0402]  (hidden comment: ERJ-2GE0R00X)
R298  ValueDisplayed: 0  [0402]  (hidden comment: ERJ-2GE0R00X)
U36  TS3A5018RSVR  [RSV0016A]

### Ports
60PIN_JTAG_TCK, 60PIN_JTAG_TDI, 60PIN_JTAG_TDO_SOP0, 60PIN_JTAG_TMS, 60PIN_PGOOD_3V3, DMM_MUX_IN, MUX_IN_12 (in), PMIC_EN, RADAR_BSS_LOGGER_SPIB_CS, RADAR_DMM_CLK, RADAR_DMM_SYNC, RADAR_DP0, RADAR_DP1, RADAR_DP2, RADAR_DP3, RADAR_DP4, RADAR_DP5, RADAR_DP6, RADAR_DP7, RADAR_DP8, RADAR_DP9, RADAR_DP10, RADAR_DP11, RADAR_DP12, RADAR_DP13, RADAR_DP14, RADAR_DP15, RADAR_GPIO_0, RADAR_GPIO_1, RADAR_GPIO_2, RADAR_HOSTINTR1, RADAR_LVDS_0M, RADAR_LVDS_0P, RADAR_LVDS_1M, RADAR_LVDS_1P, RADAR_LVDS_2M, RADAR_LVDS_2P, RADAR_LVDS_3M, RADAR_LVDS_3P, RADAR_LVDS_CLKM, RADAR_LVDS_CLKP, RADAR_LVDS_FRCLKM, RADAR_LVDS_FRCLKP, RADAR_LVDS_VALIDM, RADAR_LVDS_VALIDP, RADAR_MCUCLKOUT, RADAR_MSS_LOGGER_SPIB_CLK, RADAR_NERR_IN, RADAR_NERR_OUT, RADAR_NRST, RADAR_OSC_CLKOUT, RADAR_PMIC_CLKOUT_SOP2, RADAR_RS232RX, RADAR_RS232TX, RADAR_SCL, RADAR_SDA, RADAR_SPI_CLK1, RADAR_SPI_CS1, RADAR_SPI_MISO1, RADAR_SPI_MOSI1, RADAR_SYNC_IN, RADAR_SYNC_OUT_SOP1, RADAR_WARMRST, XDSET_TCK, XDSET_TDI, XDSET_TDO, XDSET_TMS

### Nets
5V_IN: J4.2 R232.2
BRD_3V3: C117.1 J4.4 J4.6 J17.52 J17.54 R34.2 R37.2 U36.14(V+)
CB_PMIC_1V0: J4.1 J4.3
CB_PMIC_1V2: J4.5 J4.7
CB_PMIC_1V8: J4.9
GND: C117.2 J3.2 J3.3 J4.20 J4.26 J4.32 J4.38 J4.44 J4.50 J4.MP1(GND) J4.MP2(GND) J4.MP3(GND) J4.MP4(GND) J17.19 J17.25 J17.28 J17.30 J17.31 J17.32 J17.37 J17.43 J17.56 J17.MP1(GND) J17.MP2(GND) J17.MP3(GND) J17.MP4(GND) J18.2 J18.5 J18.6 J18.9 J18.10 J18.13 J18.14 J19.4 J19.8 J19.10 J19.12 J20.3 J20.4 J20.9 J20.10 J20.15 J20.16 R41.1 U36.6(GND)
VPP_1P7: J17.57
14PIN_RTCK: J19.9 R44.2
14PIN_TCK: J19.11 R44.1 U36.1(NO1)
14PIN_TDI: J19.3 U36.8(NO3)
14PIN_TDO: J19.7 U36.11(NO4)
14PIN_TMS: J19.1 U36.4(NO2)
14PIN_TRST: J19.2
60PIN_JTAG_TCK: J4.15 U36.2(COM1) ; port 60PIN_JTAG_TCK
60PIN_JTAG_TDI: J4.11 U36.7(COM3) ; port 60PIN_JTAG_TDI
60PIN_JTAG_TDO_SOP0: J4.17 U36.10(COM4) ; port 60PIN_JTAG_TDO_SOP0
60PIN_JTAG_TMS: J4.13 U36.5(COM2) ; port 60PIN_JTAG_TMS
60PIN_PGOOD_3V3: J4.14 ; port 60PIN_PGOOD_3V3
DMM_MUX_IN: J18.1 ; port DMM_MUX_IN
DMM_TRACE_CLK: J18.4 R36.1
DMM_TRACE_CTL: J18.3 R35.2
DMM_TRACE_D0: J18.7 R38.2
DMM_TRACE_D1: J18.8 R39.1
DMM_TRACE_D2: J18.11 R40.2
DMM_TRACE_D3: J18.12 R42.1
DMM_TRACE_D4: J18.15 R45.2
DMM_TRACE_D5: J18.16 R46.1
DMM_TRACE_D6: J20.1 R52.2
DMM_TRACE_D7: J20.2 R53.1
DMM_TRACE_D8: J20.5 R233.2
DMM_TRACE_D9: J20.6 R234.1
DMM_TRACE_D10: J20.7 R273.2
DMM_TRACE_D11: J20.8 R294.1
DMM_TRACE_D12: J20.11 R295.2
DMM_TRACE_D13: J20.12 R296.1
DMM_TRACE_D14: J20.13 R297.2
DMM_TRACE_D15: J20.14 R298.1
MUX_IN_12: R37.1 U36.15(IN) ; port MUX_IN_12
PMIC_EN: J17.50 ; port PMIC_EN
RADAR_BSS_LOGGER_SPIB_CS: J4.43 ; port RADAR_BSS_LOGGER_SPIB_CS
RADAR_DMM_CLK: J4.10 R36.2 ; port RADAR_DMM_CLK
RADAR_DMM_SYNC: J4.8 R35.1 ; port RADAR_DMM_SYNC
RADAR_DP0: J4.27 R38.1 ; port RADAR_DP0
RADAR_DP1: J4.29 R39.2 ; port RADAR_DP1
RADAR_DP2: J4.31 R40.1 ; port RADAR_DP2
RADAR_DP3: J4.33 R42.2 ; port RADAR_DP3
RADAR_DP4: J4.35 R45.1 ; port RADAR_DP4
RADAR_DP5: J4.37 R46.2 ; port RADAR_DP5
RADAR_DP6: J4.39 R52.1 ; port RADAR_DP6
RADAR_DP7: J4.41 R53.2 ; port RADAR_DP7
RADAR_DP8: J17.48 R233.1 ; port RADAR_DP8
RADAR_DP9: J17.46 R234.2 ; port RADAR_DP9
RADAR_DP10: J17.44 R273.1 ; port RADAR_DP10
RADAR_DP11: J17.42 R294.2 ; port RADAR_DP11
RADAR_DP12: J17.40 R295.1 ; port RADAR_DP12
RADAR_DP13: J17.38 R296.2 ; port RADAR_DP13
RADAR_DP14: J17.36 R297.1 ; port RADAR_DP14
RADAR_DP15: J17.34 R298.2 ; port RADAR_DP15
RADAR_GPIO_0: J4.56 ; port RADAR_GPIO_0
RADAR_GPIO_1: J4.58 ; port RADAR_GPIO_1
RADAR_GPIO_2: J4.60 ; port RADAR_GPIO_2
RADAR_HOSTINTR1: J4.16 ; port RADAR_HOSTINTR1
RADAR_LVDS_0M: J4.48 ; port RADAR_LVDS_0M
RADAR_LVDS_0P: J4.46 ; port RADAR_LVDS_0P
RADAR_LVDS_1M: J4.42 ; port RADAR_LVDS_1M
RADAR_LVDS_1P: J4.40 ; port RADAR_LVDS_1P
RADAR_LVDS_2M: J17.21 ; port RADAR_LVDS_2M
RADAR_LVDS_2P: J17.23 ; port RADAR_LVDS_2P
RADAR_LVDS_3M: J17.27 ; port RADAR_LVDS_3M
RADAR_LVDS_3P: J17.29 ; port RADAR_LVDS_3P
RADAR_LVDS_CLKM: J4.36 ; port RADAR_LVDS_CLKM
RADAR_LVDS_CLKP: J4.34 ; port RADAR_LVDS_CLKP
RADAR_LVDS_FRCLKM: J4.30 ; port RADAR_LVDS_FRCLKM
RADAR_LVDS_FRCLKP: J4.28 ; port RADAR_LVDS_FRCLKP
RADAR_LVDS_VALIDM: J17.39 ; port RADAR_LVDS_VALIDM
RADAR_LVDS_VALIDP: J17.41 ; port RADAR_LVDS_VALIDP
RADAR_MCUCLKOUT: J4.47 ; port RADAR_MCUCLKOUT
RADAR_MSS_LOGGER_SPIB_CLK: J4.18 ; port RADAR_MSS_LOGGER_SPIB_CLK
RADAR_NERR_IN: J4.52 ; port RADAR_NERR_IN
RADAR_NERR_OUT: J4.54 ; port RADAR_NERR_OUT
RADAR_NRST: J4.12 ; port RADAR_NRST
RADAR_OSC_CLKOUT: J4.45 R14.1 ; port RADAR_OSC_CLKOUT
RADAR_PMIC_CLKOUT_SOP2: J4.49 ; port RADAR_PMIC_CLKOUT_SOP2
RADAR_RS232RX: J4.57 ; port RADAR_RS232RX
RADAR_RS232TX: J4.59 ; port RADAR_RS232TX
RADAR_SCL: J4.55 ; port RADAR_SCL
RADAR_SDA: J4.53 ; port RADAR_SDA
RADAR_SPI_CLK1: J4.21 ; port RADAR_SPI_CLK1
RADAR_SPI_CS1: J4.19 ; port RADAR_SPI_CS1
RADAR_SPI_MISO1: J4.25 ; port RADAR_SPI_MISO1
RADAR_SPI_MOSI1: J4.23 ; port RADAR_SPI_MOSI1
RADAR_SYNC_IN: J4.22 ; port RADAR_SYNC_IN
RADAR_SYNC_OUT_SOP1: J4.24 ; port RADAR_SYNC_OUT_SOP1
RADAR_WARMRST: J4.51 ; port RADAR_WARMRST
XDSET_TCK: U36.16(NC1) ; port XDSET_TCK
XDSET_TDI: U36.9(NC3) ; port XDSET_TDI
XDSET_TDO: U36.12(NC4) ; port XDSET_TDO
XDSET_TMS: U36.3(NC2) ; port XDSET_TMS
NetJ3_1: J3.1 R14.2
NetJ17_58: J17.58 J17.59 J17.60 R232.1
NetJ19_5: J19.5 R34.1
NetR41_2: R41.2 U36.13(~{EN})

Not connected (* = marked no-connect by the designer): J17 1* 2* 3* 4* 5* 6* 7* 8* 9* 10* 11* 12* 13* 14* 15* 16* 17* 18* 20* 22* 24* 26* 33* 35* 45* 47* 49* 51* 53* 55*; J19 13* 14*

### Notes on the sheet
- HD CONNECTOR FOR LVDS AND JTAG
- JTAG DEBUG CONNECTOR
- JTAG TRACE DMM INTERFACE HEADER
- XDS/14PIN JTAG SELECTION
- MUX JUMPER CONFIG
- S1.12 OFF      : 14PIN
- S1.12 ON        : XDS110

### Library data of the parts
C117 = CMP-0078241-1: CAP, CERM, 0.1 µF, 10 V,+/- 10%, X7R, 0402; Manufacturer: Kemet; TaMin_C: -55°C; Polarized: N; SizeAreaWB_mm2: 3; U/M: EA; Value: 0.1uF; TaMax_C: 125°C; SizeZ_mm: 0.6; SizeX_mm: 1; SizeY_mm: 0.5; Value2: 10V; CompType: Capacitor; Cap_F: 100nF; AEC Category: Q200
J3 = CMP-0055788-1: UMC Straight Jack Receptacle, 50 Ohm, Gold, SMT; Manufacturer: Cinch Connectivity; CNHeader: FALSE; Gender: Female
J4 J17 = CMP-0075558-2: Header(Shrouded), 19.7mil, 30x2, Gold, SMT; Manufacturer: Samtec; Pitch_mm: 0.5; Gender: Male; Green_REACh: Passed; CT: False; Shrouded: Y; Green_Lifecycle: Active; Row_Count: 2
J18 J20 = CMP-0075418-1: Header, 100mil, 8x2, Gold, TH; Manufacturer: Samtec; Pitch_mm: 2.54; Cert_VDE: N; Gender: Male; Cert_CSA: Y; Voltage_V: 550V; Green_REACh: Passed; Current_A: 6.3A; CT: False; Green_Lifecycle: Active; Row_Count: 2; CNHeader: True
J19 = CMP-0081507-3: Header, 2.54mm, 13Pos, Gold with Tin tail, TH; Manufacturer: Samtec; Cert_UL: Y; Gender: Male; Pitch_mm: 2.54; Row_Count: 2; Shrouded: N
R14 = CMP-0027008-3: as R77 on sheet PROC074B_LP_Connector
R34 = CMP-0026993-2: RES, 100, 5%, 0.1 W, AEC-Q200 Grade 0, 0402; Manufacturer: Panasonic; Power_W: 100mW; TempCo: 200 ppm/C; Value_Code: 100R; U/M: EA; Value: 100; EIA_Code: E24; SizeX_mm: 1; SizeY_mm: 0.5; SizeZ_mm: 0.6; Value2: 0.1W; AEC Qualified: Y; AEC Grade: 0; AEC Category: Q200
R35 R36 R38-R40 R42 R45 R46 R52 R53 R233 R234 R273 R294-R298 = CMP-0026992-3: as R75 on sheet PROC074B_LP_Connector
R37 = CMP-0025958-2: RES, 10.0 k, 1%, 0.063 W, 0402; Manufacturer: Vishay-Dale; Power_W: 63mW; TempCo: 100 ppm/C; Value_Code: 10k0; U/M: EA; Value: 10.0k; EIA_Code: E96; Res_ohm: 10k; SizeX_mm: 1; SizeY_mm: 0.5; SizeZ_mm: 0.6; Value2: 0.063W; VDC_V: 50V; AEC Category: Q200
R41 = CMP-0026938-5: RES, 4.7 k, 5%, 0.063 W, AEC-Q200 Grade 0, 0402; Manufacturer: Vishay-Dale; Power_W: 63mW; TempCo: 200 ppm/C; Value_Code: 4k70; Value: 4.7k; EIA_Code: E24; SizeX_mm: 1; SizeY_mm: 0.5; SizeZ_mm: 0.6; Value2: 0.063W; AEC Qualified: Y; VDC_V: 50V; AEC Category: Q200; AEC Grade: 0
R44 = CMP-0026992-3: as R224 on sheet PROC074B_LP_Connector
R232 = CMP-0081623-1: as R122 on sheet PROC074B_LP_Connector
U36 = CMP-0067415-1: 10-Ohm Quad SPDT Analog Switch, RSV0016A (UQFN-16); Alternate Manufacturer: Texas Instruments; SizeAreaWB_mm2: 10.08; U/M: EA; SizeZ_mm: 0.55; SizeX_mm: 1.8; SizeY_mm: 2.6; SizeArea_mm2: 4.68; CompType: IC

## Sheet PROC074B_XDS110_Interface_1A.SchDoc
size 431 x 279 mm; Date: Not shown in title block; ApprovedBy: Not shown in title block; CheckedBy: Not shown in title block; Author: Not shown in title block; CompanyName: Not shown in title block; Engineer: Not shown in title block; Organization: Not shown in title block; Address1: Not shown in title block; Address2: Not shown in title block; Address3: Not shown in title block; Address4: Not shown in title block; DocumentNumber: 1; Revision: Use project parameter SCH_Rev; SheetNumber: 11; SheetTotal: 22; PageSetup: Record=PageOptions¦CenterHorizontal=True¦CenterVertical=True¦PrintScale=1.00¦XCorrection=1.00¦YCorrection=1.00¦PrintKind=0¦BorderSize=5000000¦LeftOffset=0¦BottomOffset=0¦Orientation=2¦PaperLength=1000¦PaperWidth=1000¦Scale=100¦PaperSource=15¦PrintQuality=600¦MediaType=1¦DitherType=10¦PaperKind=Letter¦PrintScaleMode=1
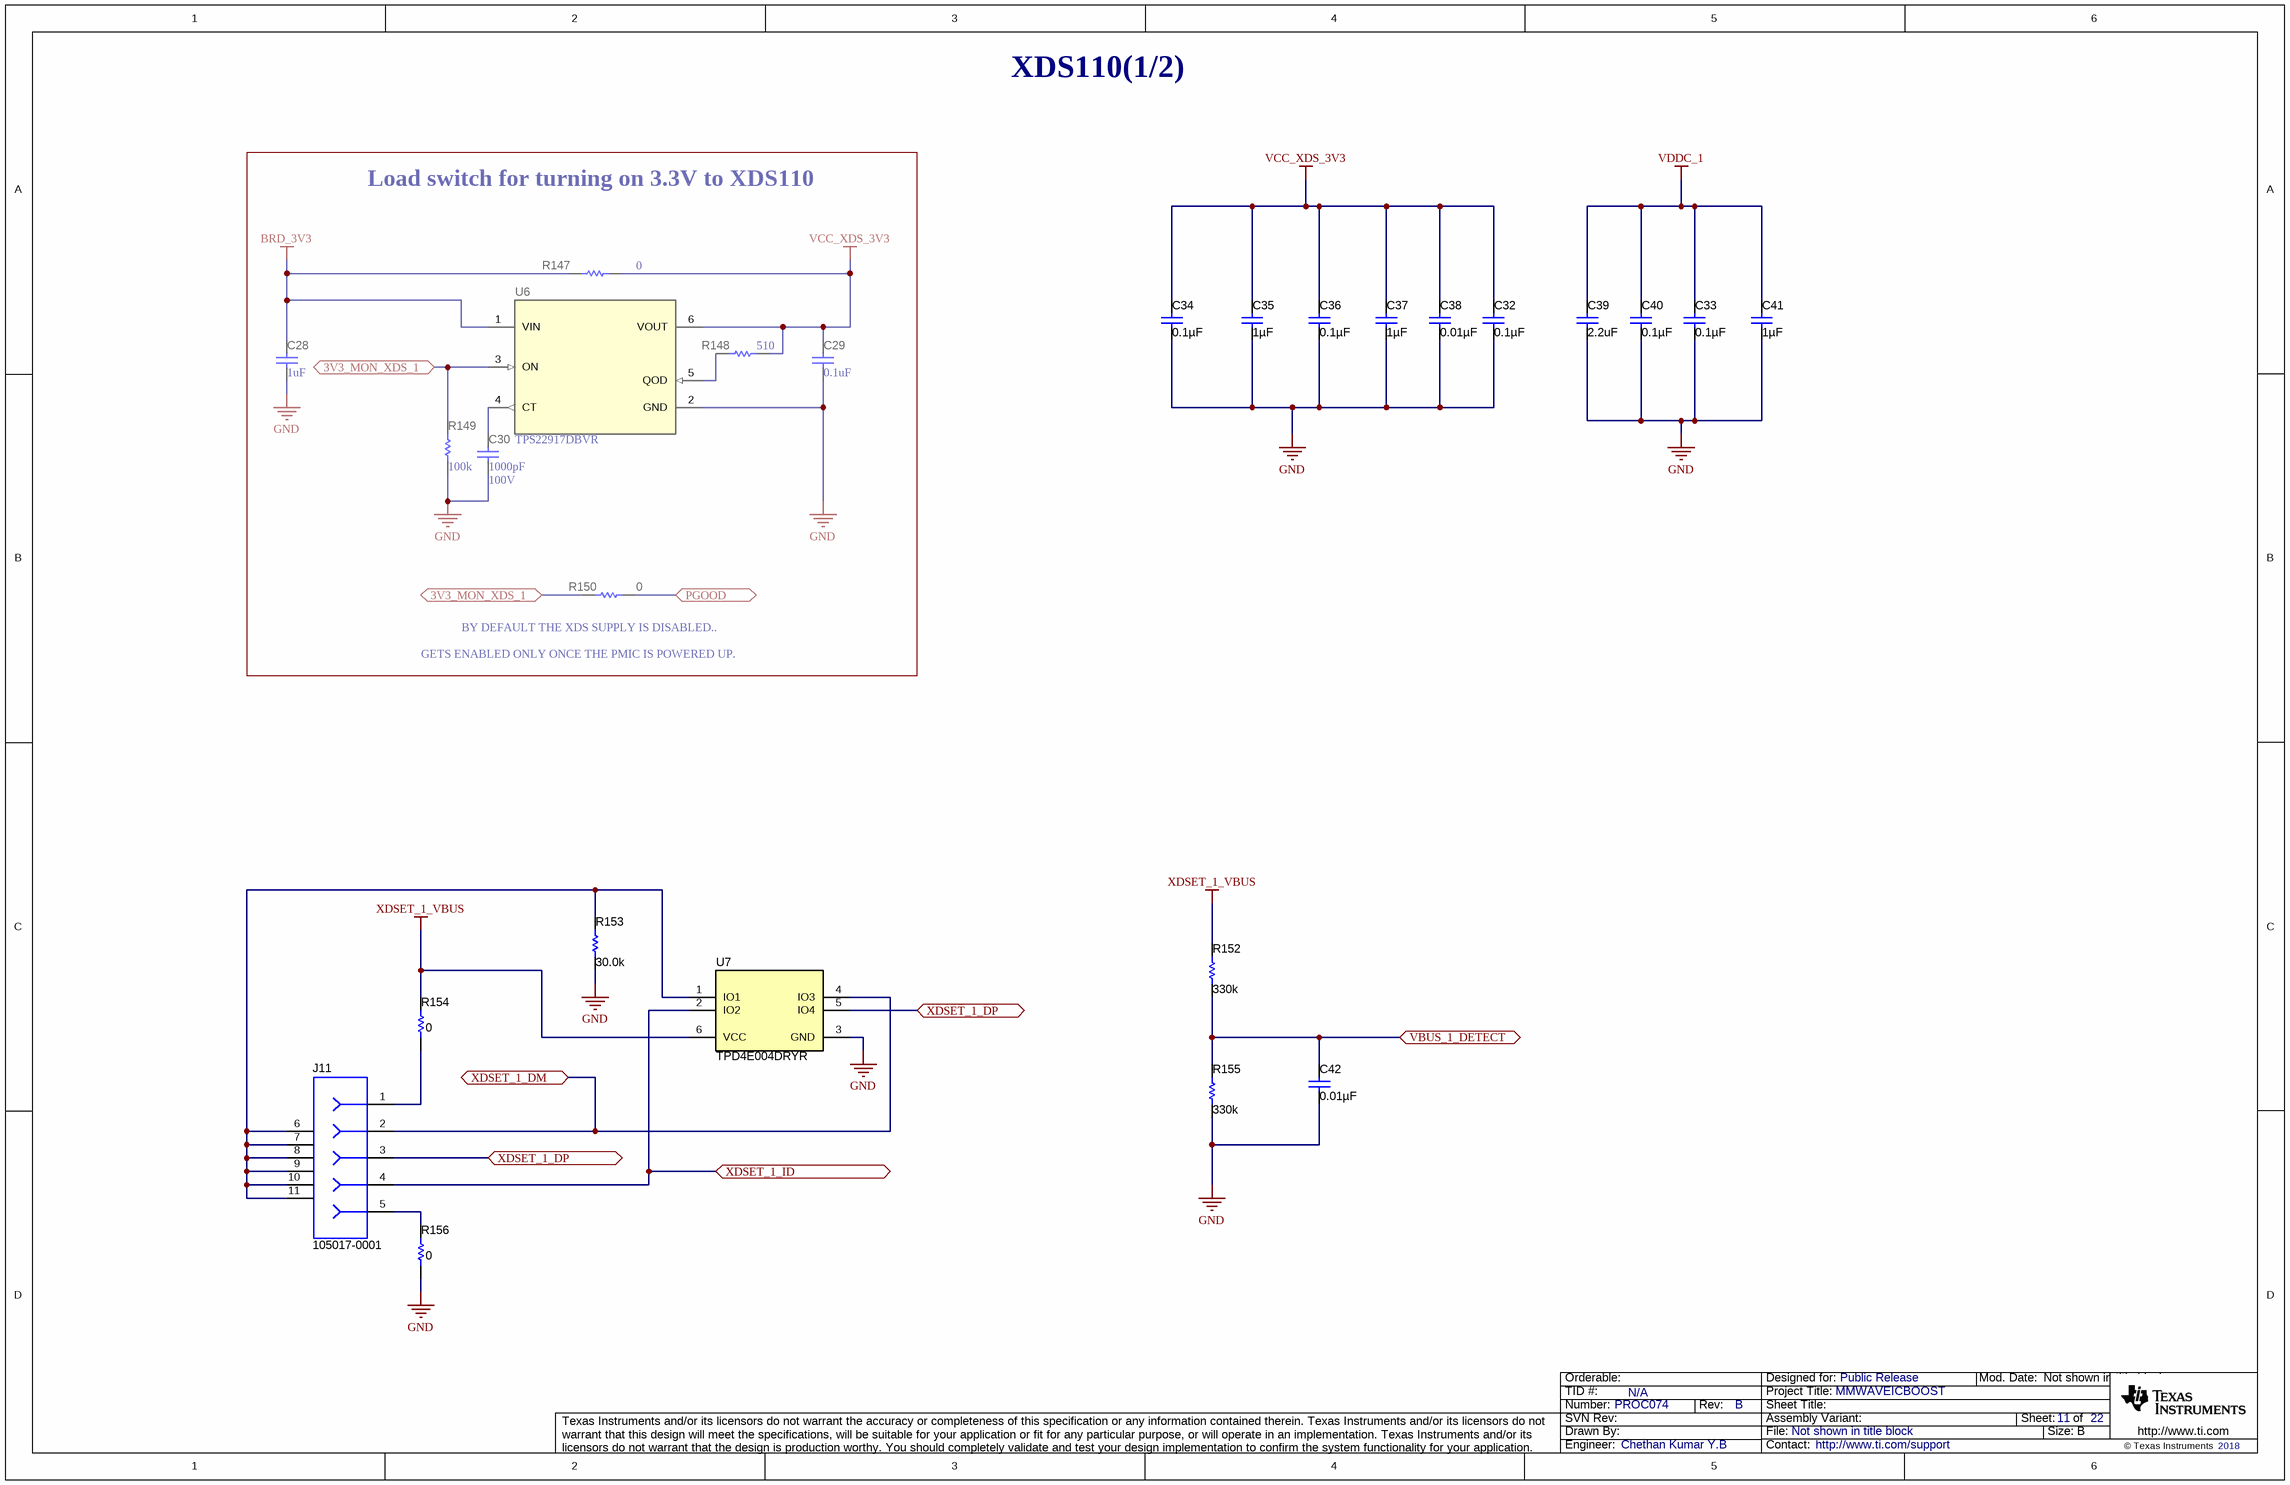
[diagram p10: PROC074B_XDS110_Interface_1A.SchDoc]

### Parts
C28  ValueDisplayed: 1uF  [0603]  (hidden comment: CL10B105KQ8NNNC)
C29  ValueDisplayed: 0.1uF  [0603]  (hidden comment: GRM188R70J104KA01D)
C30  VDC_V: 100V  ValueDisplayed: 1000pF  [0402]  (hidden comment: CGA2B3X7S2A102K050BB)
C32  ValueDisplayed: 0.1µF  [0402L]  (hidden comment: C0402C104K8RACTU)
C33  ValueDisplayed: 0.1µF  [0402L]  (hidden comment: C0402C104K8RACTU)
C34  ValueDisplayed: 0.1µF  [0402L]  (hidden comment: C0402C104K8RACTU)
C35  ValueDisplayed: 1µF  [0402L]  (hidden comment: C1005X7S0J105M050BC)
C36  ValueDisplayed: 0.1µF  [0402L]  (hidden comment: C0402C104K8RACTU)
C37  ValueDisplayed: 1µF  [0402L]  (hidden comment: C1005X7S0J105M050BC)
C38  ValueDisplayed: 0.01µF  [0402L]  (hidden comment: C1005X7R1E103K050BB)
C39  ValueDisplayed: 2.2uF  [0402_065L]  (hidden comment: C1005X7S1A225K050BC)
C40  ValueDisplayed: 0.1µF  [0402L]  (hidden comment: C0402C104K8RACTU)
C41  ValueDisplayed: 1µF  [0402L]  (hidden comment: C1005X7S0J105M050BC)
C42  ValueDisplayed: 0.01µF  [0402L]  (hidden comment: C0402C103K4RACTU)
J11  105017-0001  [CONN_105017-0001]
R147  ValueDisplayed: 0  [0603]  (hidden comment: RCS06030000Z0EA)
R148  ValueDisplayed: 510  [0402]  (hidden comment: CRCW0402510RJNED)
R149  ValueDisplayed: 100k  [0402]  (hidden comment: ERJ-2RKF1003X)
R150  ValueDisplayed: 0  [0402L]  (hidden comment: ERJ-2GE0R00X)
R152  ValueDisplayed: 330k  [0402L]  (hidden comment: CRCW0402330KFKED)
R153  ValueDisplayed: 30.0k  [0402L]  (hidden comment: CRCW040230K0FKED)
R154  ValueDisplayed: 0  [0603]  (hidden comment: MCT06030Z0000ZP500)
R155  ValueDisplayed: 330k  [0402L]  (hidden comment: CRCW0402330KFKED)
R156  ValueDisplayed: 0  [0603]  (hidden comment: MCT06030Z0000ZP500)
U6  TPS22917DBVR  [DBV0006A_L]
U7  TPD4E004DRYR  [DRY0006A]

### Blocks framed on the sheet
Load switch for turning on 3.3V to XDS110: C28-C30 R147-R150 U6

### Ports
3V3_MON_XDS_1, PGOOD, VBUS_1_DETECT, XDSET_1_DM, XDSET_1_DP, XDSET_1_ID

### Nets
BRD_3V3: C28.1 R147.1 U6.1(VIN)
GND: C28.2 C29.2 C30.2 C32.1 C33.1 C34.1 C35.1 C36.1 C37.1 C38.1 C39.1 C40.1 C41.1 C42.1 R149.1 R153.1 R155.1 R156.1 U6.2(GND) U7.3(GND)
VCC_XDS_3V3: C29.1 C32.2 C34.2 C35.2 C36.2 C37.2 C38.2 R147.2 R148.1 U6.6(VOUT)
VDDC_1: C33.2 C39.2 C40.2 C41.2
XDSET_1_VBUS: R152.2 R154.2 U7.6(VCC)
3V3_MON_XDS_1: R149.2 R150.2 U6.3(ON) ; port 3V3_MON_XDS_1
PGOOD: R150.1 ; port PGOOD
VBUS_1_DETECT: C42.2 R152.1 R155.2 ; port VBUS_1_DETECT
XDSET_1_DM: J11.2 U7.4(IO3) ; port XDSET_1_DM
XDSET_1_DP: J11.3 U7.5(IO4) ; port XDSET_1_DP
XDSET_1_ID: J11.4 U7.2(IO2) ; port XDSET_1_ID
NetC30_1: C30.1 U6.4(CT)
NetJ11_1: J11.1 R154.1
NetJ11_5: J11.5 R156.2
NetJ11_6: J11.6 J11.7 J11.8 J11.9 J11.10 J11.11 R153.2 U7.1(IO1)
NetR148_2: R148.2 U6.5(QOD)

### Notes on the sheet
- XDS110(1/2)
- (near R150) BY DEFAULT THE XDS SUPPLY IS DISABLED..
- GETS ENABLED ONLY ONCE THE PMIC IS POWERED UP.

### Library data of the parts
C28 = CMP-0007111-4: CAP, CERM, 1 uF, 6.3 V, +/- 10%, X7R, 0603; Manufacturer: Samsung Electro-Mechanics; TaMin_C: -55°C; Polarized: N; SizeAreaWB_mm2: 4.68; Value1: Unknown; U/M: EA; Value: 1uF; TaMax_C: 125°C; SizeZ_mm: 1; SizeX_mm: 1.6; SizeY_mm: 0.8; Value2: 6.3V; SizeArea_mm2: 1.28; CompType: Capacitor; Cap_F: 1µF; AEC Category: Q200
C29 = CMP-0007359-4: CAP, CERM, 0.1 uF, 6.3 V, +/- 10%, X7R, 0603; Manufacturer: MuRata; TaMin_C: -55°C; Polarized: N; SizeAreaWB_mm2: 4.68; Value1: Unknown; U/M: EA; Value: 0.1uF; TaMax_C: 125°C; SizeZ_mm: 1; SizeX_mm: 1.6; SizeY_mm: 0.8; Value2: 6.3V; SizeArea_mm2: 1.28; CompType: Capacitor; Cap_F: 100nF; AEC Category: Q200
C30 = CMP-0006332-2: CAP, CERM, 1000 pF, 100 V, +/- 10%, X7S, AEC-Q200 Grade 1, 0402; Manufacturer: TDK; TaMin_C: -55°C; ESR_ohm: 2.71151; Polarized: N; SizeAreaWB_mm2: 3; Value1: 2.71151 ohm; U/M: EA; Value: 1000pF; TaMax_C: 125°C; SizeZ_mm: 0.6; SizeX_mm: 1; SizeY_mm: 0.5; AEC Qualified: Y; Cap_F: 1nF; IRMS_A: 2.64589dA; AEC Category: Q200
C32-C34 C36 C40 = CMP-0078241-1: CAP, CERM, 0.1 µF, 10 V,+/- 10%, X7R, 0402; Manufacturer: Kemet; TaMin_C: -55°C; Polarized: N; SizeAreaWB_mm2: 3; U/M: EA; Value: 0.1uF; TaMax_C: 125°C; SizeZ_mm: 0.6; SizeX_mm: 1; SizeY_mm: 0.5; Cap_Case: 0402; Value2: 10V; CompType: Capacitor; Cap_F: 100nF; AEC Category: Q200
C35 C37 C41 = CMP-0078222-1: CAP, CERM, 1 µF, 6.3 V,+/- 20%, X7S, 0402; Manufacturer: TDK; TaMin_C: -55°C; Polarized: N; SizeAreaWB_mm2: 3; U/M: EA; Value: 1uF; TaMax_C: 125°C; SizeZ_mm: 0.6; SizeX_mm: 1; SizeY_mm: 0.5; Cap_Case: 0402; Value2: 6.3V; CompType: Capacitor; AEC Category: Q200
C38 = CMP-0078220-1: CAP, CERM, 0.01 µF, 25 V,+/- 10%, X7R, 0402; Manufacturer: TDK; TaMin_C: -55°C; Polarized: N; Green_Lifecycle: NRND; SizeAreaWB_mm2: 3; Green_REACh: Passed; U/M: EA; Value: 0.01uF; TaMax_C: 125°C; SizeZ_mm: 0.6; SizeX_mm: 1; SizeY_mm: 0.5; Cap_Case: 0402; Value2: 25V; CompType: Capacitor; Cap_F: 10nF; AEC Category: Q200
C39 = CMP-0006302-2: CAP, CERM, 2.2 uF, 10 V, +/- 10%, X7S, 0402; Manufacturer: TDK; TaMin_C: -55°C; ESR_ohm: 5.925m; Polarized: N; SizeAreaWB_mm2: 3; Value1: 0.005925 ohm; U/M: EA; Value: 2.2uF; TaMax_C: 125°C; SizeZ_mm: 0.65; SizeX_mm: 1; SizeY_mm: 0.5; Cap_Case: 0402_065; Value2: 10V; CompType: Capacitor; Cap_F: 2.2µF; IRMS_A: 2.05591A; AEC Category: Q200
C42 = CMP-0078218-1: CAP, CERM, 0.01 µF, 16 V,+/- 10%, X7R, 0402; Manufacturer: Kemet; TaMin_C: -55°C; Polarized: N; Green_Lifecycle: Active; SizeAreaWB_mm2: 3; Green_REACh: Passed; U/M: EA; Value: 0.01uF; TaMax_C: 125°C; SizeZ_mm: 0.6; SizeX_mm: 1; SizeY_mm: 0.5; Cap_Case: 0402; Value2: 16V; CompType: Capacitor; Cap_F: 10nF; AEC Category: Q200
J11 = CMP-0055293-1: Connector, Receptacle, Micro-USB Type B, R/A, Bottom Mount SMT; Manufacturer: Molex; CNHeader: FALSE; Green_Lifecycle: Active; Gender: Female; Green_REACh: Passed; CompType: USB; CT: TRUE
R147 = CMP-0081973-1: RES, 0, 0%, 0.25 W, AEC-Q200 Grade 0, 0603; Manufacturer: Vishay-Dale; SizeAreaWB_mm2: 4.68; SizeArea_mm2: 1.28; AEC Qualified: Y; AEC Category: Q200; Value: 0; SizeZ_mm: 1; SizeY_mm: 0.8; Power_W: 250mW; Value2: 0.25W; CompType: Resistor; SizeX_mm: 1.6; INSTALLATION: DNP
R148 = CMP-0026944-3: RES, 510, 5%, 0.063 W, AEC-Q200 Grade 0, 0402; Manufacturer: Vishay-Dale; Power_W: 63mW; TempCo: 200 ppm/C; Value_Code: 510R; Value: 510; EIA_Code: E24; SizeX_mm: 1; SizeY_mm: 0.5; SizeZ_mm: 0.6; Value2: 0.063W; AEC Qualified: Y; VDC_V: 50V; AEC Category: Q200; AEC Grade: 0
R149 = CMP-0026659-1: RES, 100 k, 1%, 0.1 W, 0402; Manufacturer: Panasonic; Power_W: 100mW; TempCo: 100 ppm/C; U/M: EA; Value: 100k; EIA_Code: E96; SizeX_mm: 1; SizeY_mm: 0.5; SizeZ_mm: 0.6; Value2: 0.1W; VDC_V: 50V; AEC Category: Q200
R150 = CMP-0026992-2: RES, 0, 5%, 0.063 W, 0402; Manufacturer: Panasonic; Power_W: 63mW; TempCo: 600 ppm/C; Value_Code: 0000; U/M: EA; Value: 0; EIA_Code: E24; SizeX_mm: 1; SizeY_mm: 0.5; SizeZ_mm: 0.6; Value2: 0.063W; VDC_V: 50V; AEC Category: Q200
R152 R155 = CMP-0078210-1: RES, 330 k, 1%, 0.063 W, AEC-Q200 Grade 0, 0402; Manufacturer: Vishay-Dale; SizeArea_mm2: 0.5; AEC Qualified: Y; AEC Category: Q200; Value: 330k; SizeZ_mm: 0.6; TempCo: 100 ppm/C; AEC Grade: 0; Power_W: 63mW; VDC_V: 50V; Value2: 0.063W; U/M: EA; SizeX_mm: 1
R153 = CMP-0078244-1: RES, 30.0 k, 1%, 0.063 W, AEC-Q200 Grade 0, 0402; Manufacturer: Vishay-Dale; Power_W: 63mW; Green_Lifecycle: Active; TempCo: 100 ppm/C; Value_Code: 30k0; Green_REACh: Passed; Value: 30.0k; Res_ohm: 30k; SizeX_mm: 1; SizeY_mm: 0.5; SizeZ_mm: 0.6; Value2: 0.063W; AEC Qualified: Y; VDC_V: 50V; AEC Grade: 0; AEC Category: Q200
R154 R156 = CMP-0025884-3: RES, 0, 5%, 0.125 W, 0603; Manufacturer: Vishay/Beyschlag; Power_W: 125mW; TempCo: ppm/C; Value_Code: 0000; U/M: EA; Value: 0; EIA_Code: E24; SizeX_mm: 1.6; SizeY_mm: 0.8; SizeZ_mm: 1; Value2: 0.125W; SizeArea_mm2: 1.28; AEC Qualified: N; AEC Category: Q200
U6 = CMP-0077265-1: 5.5-V, 2-A, 80 mohm Low Leakage Load Switch with RCB and Programmable Rise Time, DBV0006A (SOT-23-6); Alternate PartNumber: TPS22917DBVT; Alternate Manufacturer: Texas Instruments; SizeAreaWB_mm2: 14.82; SizeZ_mm: 1.45; SizeX_mm: 2.8; SizeY_mm: 2.9; SizeArea_mm2: 8.12; CompType: IC; AEC Qualified: N; AEC Category: Q200
U7 = CMP-0043115-1: ESD-Protection Array for High-Speed Data Interfaces, 4 Channels, -40 to +85 degC, 6-pin SON (DRY), Green (RoHS & no Sb/Br); Manufacturer: Texas Instruments; IO Leakage Current(nA): 1; USB High Speed: TRUE; IO Capacitance(Typ)(pF): 1.6; SubFamily: ESD Solution; IEC 61000-4-2 Contact(+/- kV): 8; Breakdown Voltage(Min)(V): 6; IEC 61000-4-2 Air-Gap(+/- kV): 12

## Sheet PROC074B_XDS110_Interface_1B.SchDoc
size 431 x 279 mm; Date: Not shown in title block; ApprovedBy: Not shown in title block; CheckedBy: Not shown in title block; Author: Not shown in title block; CompanyName: Not shown in title block; Engineer: Not shown in title block; Organization: Not shown in title block; Address1: Not shown in title block; Address2: Not shown in title block; Address3: Not shown in title block; Address4: Not shown in title block; DocumentNumber: 1; Revision: Use project parameter SCH_Rev; SheetNumber: 12; SheetTotal: 22; PageSetup: Record=PageOptions¦CenterHorizontal=True¦CenterVertical=True¦PrintScale=1.00¦XCorrection=1.00¦YCorrection=1.00¦PrintKind=0¦BorderSize=5000000¦LeftOffset=0¦BottomOffset=0¦Orientation=2¦PaperLength=1000¦PaperWidth=1000¦Scale=100¦PaperSource=15¦PrintQuality=600¦MediaType=1¦DitherType=10¦PaperKind=Letter¦PrintScaleMode=1
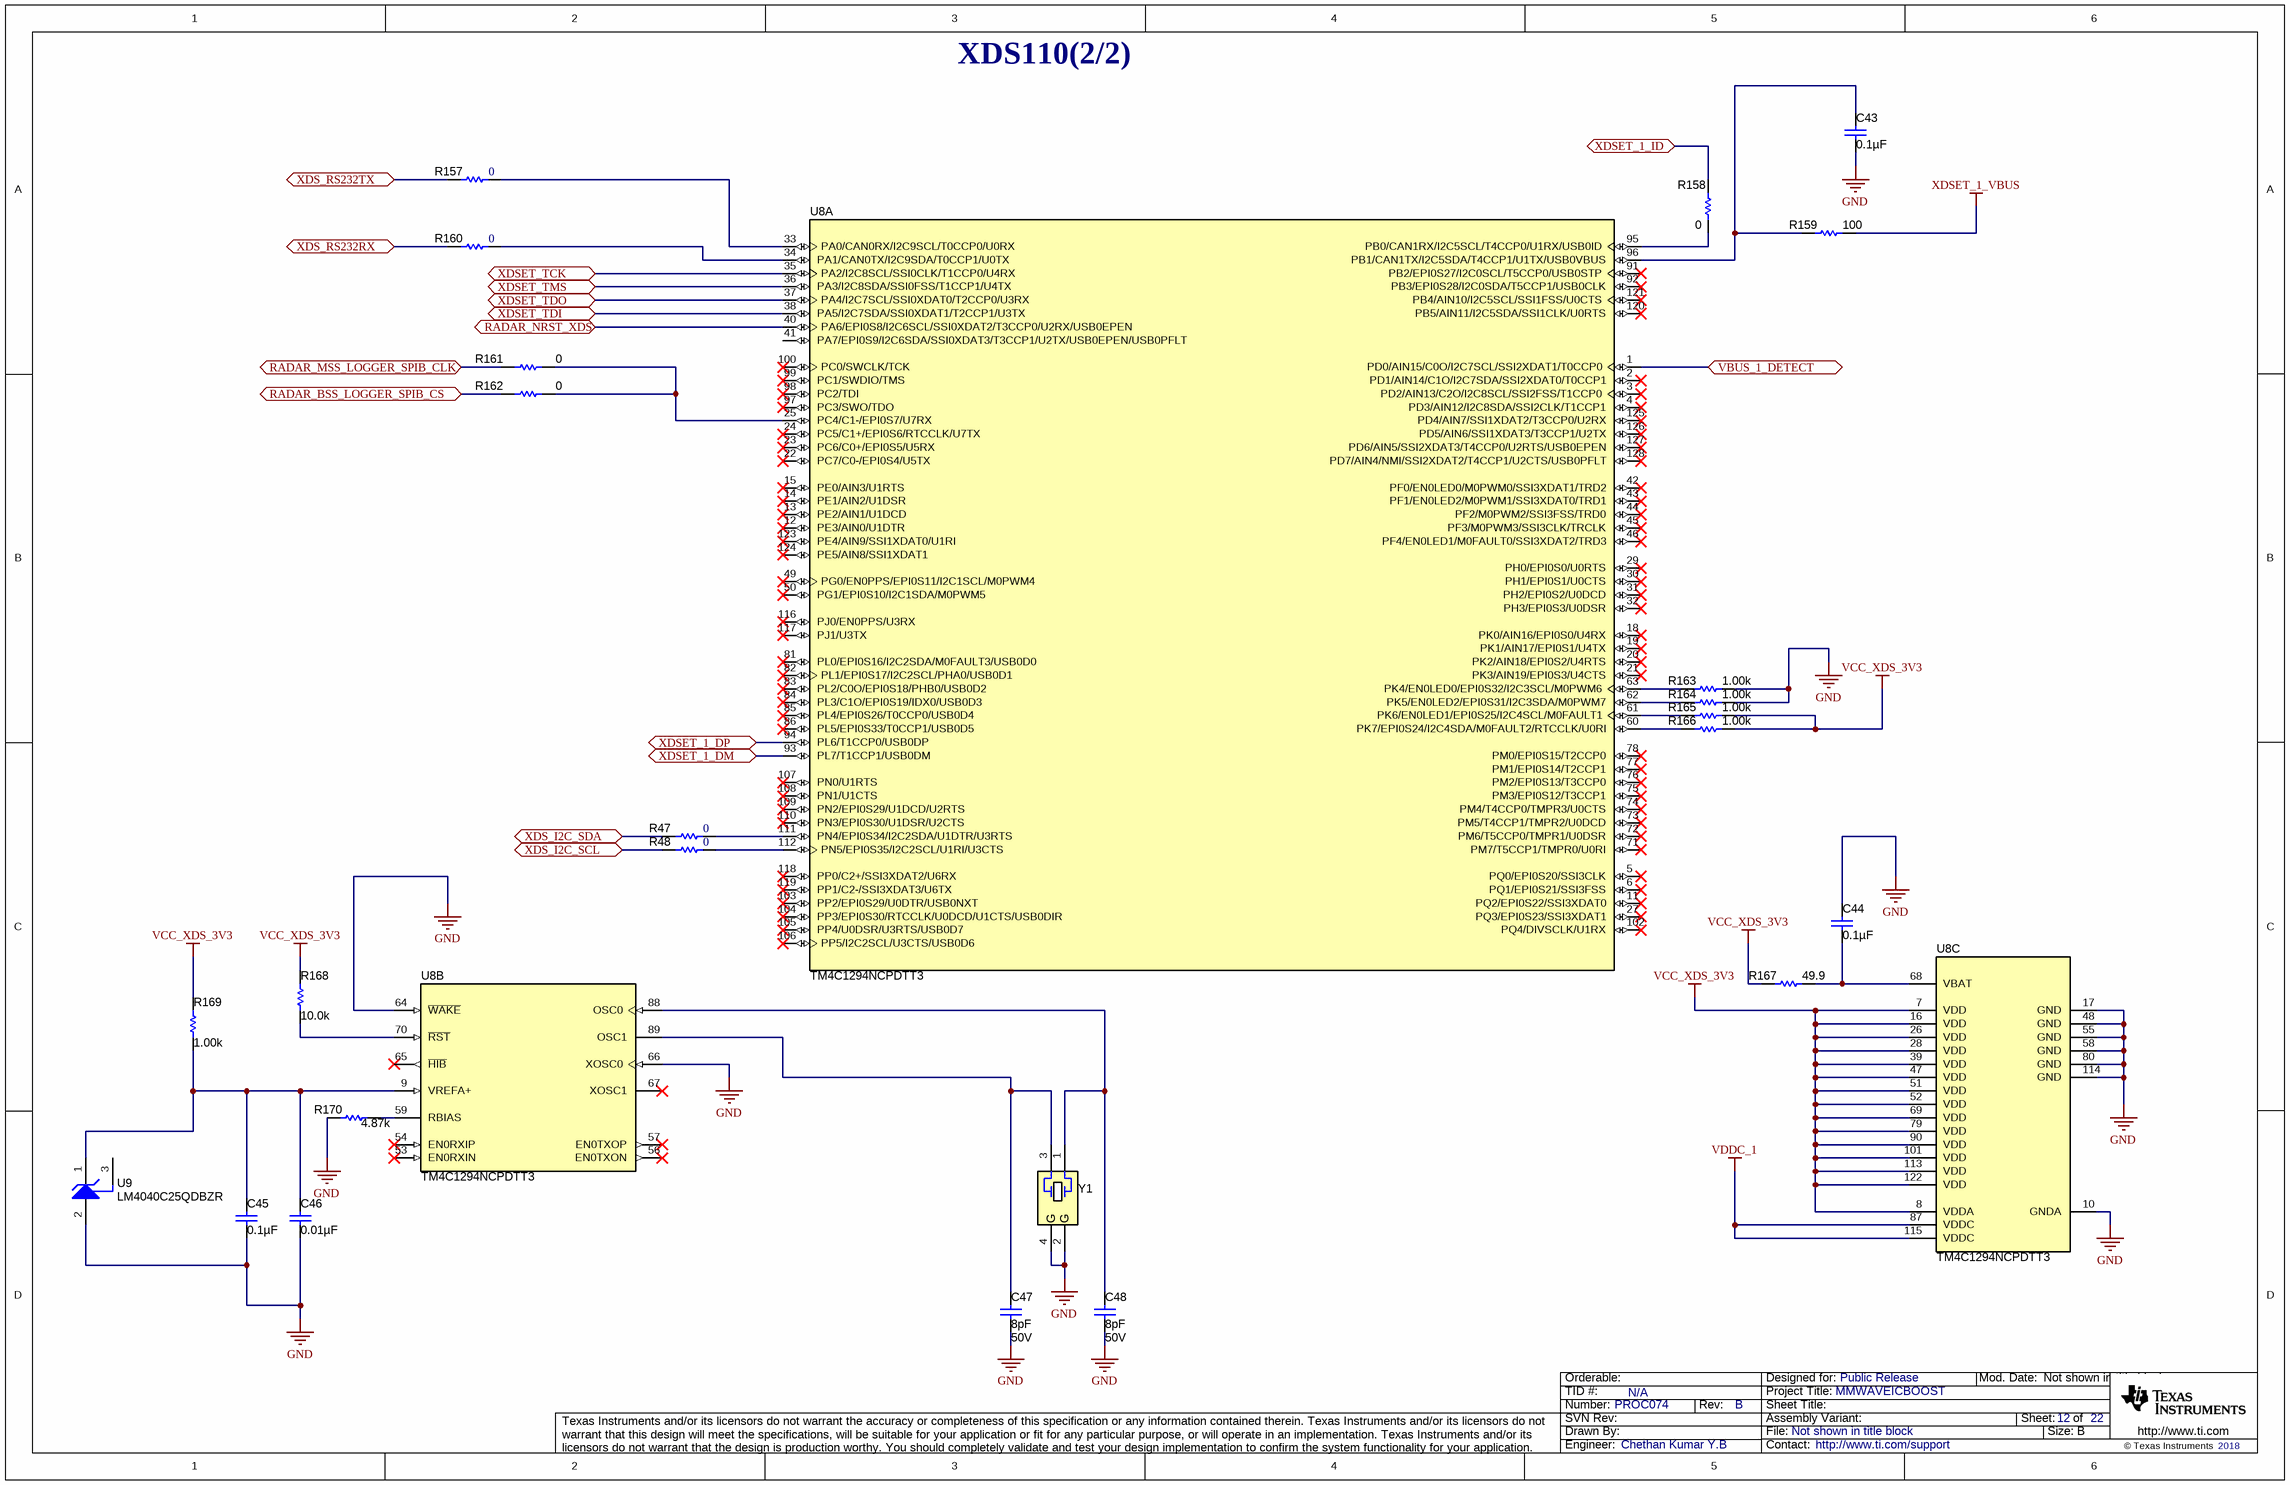
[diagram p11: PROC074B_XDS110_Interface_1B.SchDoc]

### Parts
C43  ValueDisplayed: 0.1µF  [0402L]  (hidden comment: C0402C104K8RACTU)
C44  ValueDisplayed: 0.1µF  [0402L]  (hidden comment: C0402C104K8RACTU)
C45  ValueDisplayed: 0.1µF  [0402L]  (hidden comment: C0402C104K8RACTU)
C46  ValueDisplayed: 0.01µF  [0402L]  (hidden comment: C0402C103K4RACTU)
C47  VDC_V: 50V  ValueDisplayed: 8pF  [0402L]  (hidden comment: GRM1555C1H8R0DA01D)
C48  VDC_V: 50V  ValueDisplayed: 8pF  [0402L]  (hidden comment: GRM1555C1H8R0DA01D)
R47  ValueDisplayed: 0  [0402]  (hidden comment: ERJ-2GE0R00X)
R48  ValueDisplayed: 0  [0402]  (hidden comment: ERJ-2GE0R00X)
R157  ValueDisplayed: 0  [0402]  (hidden comment: ERJ-2GE0R00X)
R158  ValueDisplayed: 0  [0402L]  (hidden comment: ERJ-2GE0R00X)
R159  ValueDisplayed: 100  [0402L]  (hidden comment: ERJ-2GEJ101X)
R160  ValueDisplayed: 0  [0402]  (hidden comment: ERJ-2GE0R00X)
R161  ValueDisplayed: 0  [0201_Silk]  (hidden comment: CRCW02010000Z0ED)
R162  ValueDisplayed: 0  [0201_Silk]  (hidden comment: CRCW02010000Z0ED)
R163  ValueDisplayed: 1.00k  [0402L]  (hidden comment: CRCW04021K00FKED)
R164  ValueDisplayed: 1.00k  [0402L]  (hidden comment: CRCW04021K00FKED)
R165  ValueDisplayed: 1.00k  [0402L]  (hidden comment: CRCW04021K00FKED)
R166  ValueDisplayed: 1.00k  [0402L]  (hidden comment: CRCW04021K00FKED)
R167  ValueDisplayed: 49.9  [0402L]  (hidden comment: CRCW040249R9FKED)
R168  ValueDisplayed: 10.0k  [0402L]  (hidden comment: CRCW040210K0FKED)
R169  ValueDisplayed: 1.00k  [0402L]  (hidden comment: CRCW04021K00FKED)
R170  ValueDisplayed: 4.87k  [0402L]  (hidden comment: CRCW04024K87FKED)
U8  TM4C1294NCPDTT3  [PDT0128A]  (parts A,B,C of 3)
U9  LM4040C25QDBZR  [DBZ0003A_N]
Y1  NX3225SA-16.000M-STD-CRS-2  [NDK_NX3225SA]  (value not drawn)

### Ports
RADAR_BSS_LOGGER_SPIB_CS, RADAR_MSS_LOGGER_SPIB_CLK, RADAR_NRST_XDS, VBUS_1_DETECT, XDS_I2C_SCL, XDS_I2C_SDA, XDS_RS232RX, XDS_RS232TX, XDSET_1_DM, XDSET_1_DP, XDSET_1_ID, XDSET_TCK, XDSET_TDI, XDSET_TDO, XDSET_TMS

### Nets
GND: C43.1 C44.1 C45.1 C46.1 C47.1 C48.1 R163.2 R164.2 R170.1 U8.10(GNDA) U8.17(GND) U8.48(GND) U8.55(GND) U8.58(GND) U8.64(~{WAKE}) U8.66(XOSC0) U8.80(GND) U8.114(GND) U9.2(ANODE) Y1.2(GND) Y1.4(GND)
VCC_XDS_3V3: R165.2 R166.2 R167.2 R168.2 R169.2 U8.7(VDD) U8.8(VDDA) U8.16(VDD) U8.26(VDD) U8.28(VDD) U8.39(VDD) U8.47(VDD) U8.51(VDD) U8.52(VDD) U8.69(VDD) U8.79(VDD) U8.90(VDD) U8.101(VDD) U8.113(VDD) U8.122(VDD)
VDDC_1: U8.87(VDDC) U8.115(VDDC)
XDSET_1_VBUS: R159.2
RADAR_BSS_LOGGER_SPIB_CS: R162.1 ; port RADAR_BSS_LOGGER_SPIB_CS
RADAR_MSS_LOGGER_SPIB_CLK: R161.1 ; port RADAR_MSS_LOGGER_SPIB_CLK
RADAR_NRST_XDS: U8.40(PA6/EPI0S8/I2C6SCL/SSI0XDAT2/T3CCP0/U2RX/USB0EPEN) ; port RADAR_NRST_XDS
VBUS_1_DETECT: U8.1(PD0/AIN15/C0O/I2C7SCL/SSI2XDAT1/T0CCP0) ; port VBUS_1_DETECT
XDS_I2C_SCL: R48.1 ; port XDS_I2C_SCL
XDS_I2C_SDA: R47.1 ; port XDS_I2C_SDA
XDS_RS232RX: R160.1 ; port XDS_RS232RX
XDS_RS232TX: R157.1 ; port XDS_RS232TX
XDSET_1_DM: U8.93(PL7/T1CCP1/USB0DM) ; port XDSET_1_DM
XDSET_1_DP: U8.94(PL6/T1CCP0/USB0DP) ; port XDSET_1_DP
XDSET_1_ID: R158.2 ; port XDSET_1_ID
XDSET_TCK: U8.35(PA2/I2C8SCL/SSI0CLK/T1CCP0/U4RX) ; port XDSET_TCK
XDSET_TDI: U8.38(PA5/I2C7SDA/SSI0XDAT1/T2CCP1/U3TX) ; port XDSET_TDI
XDSET_TDO: U8.37(PA4/I2C7SCL/SSI0XDAT0/T2CCP0/U3RX) ; port XDSET_TDO
XDSET_TMS: U8.36(PA3/I2C8SDA/SSI0FSS/T1CCP1/U4TX) ; port XDSET_TMS
NetC43_2: C43.2 R159.1 U8.96(PB1/CAN1TX/I2C5SDA/T4CCP1/U1TX/USB0VBUS)
NetC44_2: C44.2 R167.1 U8.68(VBAT)
NetC45_2: C45.2 C46.2 R169.1 U8.9(VREFA+) U9.1(CATHODE)
NetC47_2: C47.2 U8.89(OSC1) Y1.3
NetC48_2: C48.2 U8.88(OSC0) Y1.1
NetR47_2: R47.2 U8.111(PN4/EPI0S34/I2C2SDA/U1DTR/U3RTS)
NetR48_2: R48.2 U8.112(PN5/EPI0S35/I2C2SCL/U1RI/U3CTS)
NetR157_2: R157.2 U8.33(PA0/CAN0RX/I2C9SCL/T0CCP0/U0RX)
NetR158_1: R158.1 U8.95(PB0/CAN1RX/I2C5SCL/T4CCP0/U1RX/USB0ID)
NetR160_2: R160.2 U8.34(PA1/CAN0TX/I2C9SDA/T0CCP1/U0TX)
NetR161_2: R161.2 R162.2 U8.25(PC4/C1-/EPI0S7/U7RX)
NetR163_1: R163.1 U8.63(PK4/EN0LED0/EPI0S32/I2C3SCL/M0PWM6)
NetR164_1: R164.1 U8.62(PK5/EN0LED2/EPI0S31/I2C3SDA/M0PWM7)
NetR165_1: R165.1 U8.61(PK6/EN0LED1/EPI0S25/I2C4SCL/M0FAULT1)
NetR166_1: R166.1 U8.60(PK7/EPI0S24/I2C4SDA/M0FAULT2/RTCCLK/U0RI)
NetR168_1: R168.1 U8.70(~{RST})
NetR170_2: R170.2 U8.59(RBIAS)

Not connected (* = marked no-connect by the designer): U8 2(PD1/AIN14/C1O/I2C7SDA/SSI2XDAT0/T0CCP1)* 3(PD2/AIN13/C2O/I2C8SCL/SSI2FSS/T1CCP0)* 4(PD3/AIN12/I2C8SDA/SSI2CLK/T1CCP1)* 5(PQ0/EPI0S20/SSI3CLK)* 6(PQ1/EPI0S21/SSI3FSS)* 11(PQ2/EPI0S22/SSI3XDAT0)* 12(PE3/AIN0/U1DTR)* 13(PE2/AIN1/U1DCD)* 14(PE1/AIN2/U1DSR)* 15(PE0/AIN3/U1RTS)* 18(PK0/AIN16/EPI0S0/U4RX)* 19(PK1/AIN17/EPI0S1/U4TX)* 20(PK2/AIN18/EPI0S2/U4RTS)* 21(PK3/AIN19/EPI0S3/U4CTS)* 22(PC7/C0-/EPI0S4/U5TX)* 23(PC6/C0+/EPI0S5/U5RX)* 24(PC5/C1+/EPI0S6/RTCCLK/U7TX)* 27(PQ3/EPI0S23/SSI3XDAT1)* 29(PH0/EPI0S0/U0RTS)* 30(PH1/EPI0S1/U0CTS)* 31(PH2/EPI0S2/U0DCD)* 32(PH3/EPI0S3/U0DSR)* 41(PA7/EPI0S9/I2C6SDA/SSI0XDAT3/T3CCP1/U2TX/USB0EPEN/USB0PFLT) 42(PF0/EN0LED0/M0PWM0/SSI3XDAT1/TRD2)* 43(PF1/EN0LED2/M0PWM1/SSI3XDAT0/TRD1)* 44(PF2/M0PWM2/SSI3FSS/TRD0)* 45(PF3/M0PWM3/SSI3CLK/TRCLK)* 46(PF4/EN0LED1/M0FAULT0/SSI3XDAT2/TRD3)* 49(PG0/EN0PPS/EPI0S11/I2C1SCL/M0PWM4)* 50(PG1/EPI0S10/I2C1SDA/M0PWM5)* 53(EN0RXIN)* 54(EN0RXIP)* 56(EN0TXON)* 57(EN0TXOP)* 65(~{HIB})* 67(XOSC1)* 71(PM7/T5CCP1/TMPR0/U0RI)* 72(PM6/T5CCP0/TMPR1/U0DSR)* 73(PM5/T4CCP1/TMPR2/U0DCD)* 74(PM4/T4CCP0/TMPR3/U0CTS)* 75(PM3/EPI0S12/T3CCP1)* 76(PM2/EPI0S13/T3CCP0)* 77(PM1/EPI0S14/T2CCP1)* 78(PM0/EPI0S15/T2CCP0)* 81(PL0/EPI0S16/I2C2SDA/M0FAULT3/USB0D0)* 82(PL1/EPI0S17/I2C2SCL/PHA0/USB0D1)* 83(PL2/C0O/EPI0S18/PHB0/USB0D2)* 84(PL3/C1O/EPI0S19/IDX0/USB0D3)* 85(PL4/EPI0S26/T0CCP0/USB0D4)* 86(PL5/EPI0S33/T0CCP1/USB0D5)* 91(PB2/EPI0S27/I2C0SCL/T5CCP0/USB0STP)* 92(PB3/EPI0S28/I2C0SDA/T5CCP1/USB0CLK)* 97(PC3/SWO/TDO)* 98(PC2/TDI)* 99(PC1/SWDIO/TMS)* 100(PC0/SWCLK/TCK)* 102(PQ4/DIVSCLK/U1RX)* 103(PP2/EPI0S29/U0DTR/USB0NXT)* 104(PP3/EPI0S30/RTCCLK/U0DCD/U1CTS/USB0DIR)* 105(PP4/U0DSR/U3RTS/USB0D7)* 106(PP5/I2C2SCL/U3CTS/USB0D6)* 107(PN0/U1RTS)* 108(PN1/U1CTS)* 109(PN2/EPI0S29/U1DCD/U2RTS)* 110(PN3/EPI0S30/U1DSR/U2CTS)* 116(PJ0/EN0PPS/U3RX)* 117(PJ1/U3TX)* 118(PP0/C2+/SSI3XDAT2/U6RX)* 119(PP1/C2-/SSI3XDAT3/U6TX)* 120(PB5/AIN11/I2C5SDA/SSI1CLK/U0RTS)* 121(PB4/AIN10/I2C5SCL/SSI1FSS/U0CTS)* 123(PE4/AIN9/SSI1XDAT0/U1RI)* 124(PE5/AIN8/SSI1XDAT1)* 125(PD4/AIN7/SSI1XDAT2/T3CCP0/U2RX)* 126(PD5/AIN6/SSI1XDAT3/T3CCP1/U2TX)* 127(PD6/AIN5/SSI2XDAT3/T4CCP0/U2RTS/USB0EPEN)* 128(PD7/AIN4/NMI/SSI2XDAT2/T4CCP1/U2CTS/USB0PFLT)*; U9 3(NC)

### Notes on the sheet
- XDS110(2/2)

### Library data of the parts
C43-C45 = CMP-0078241-1: as C32 on sheet PROC074B_XDS110_Interface_1A
C46 = CMP-0078218-1: as C42 on sheet PROC074B_XDS110_Interface_1A
C47 C48 = CMP-0006494-2: CAP, CERM, 8 pF, 50 V, +/- 6%, C0G/NP0, 0402; Manufacturer: MuRata; TaMin_C: -55°C; Polarized: N; SizeAreaWB_mm2: 3; Value1: Unknown; U/M: EA; Value: 8pF; TaMax_C: 125°C; SizeZ_mm: 0.6; SizeX_mm: 1; SizeY_mm: 0.5; Cap_Case: 0402; CompType: Capacitor; AEC Category: Q200
R47 R48 R157 R160 = CMP-0026992-3: as R224 on sheet PROC074B_LP_Connector
R158 = CMP-0026992-2: as R150 on sheet PROC074B_XDS110_Interface_1A
R159 = CMP-0026993-2: as R34 on sheet PROC074B_HD_Conn_JTAG_HDR
R161 = CMP-0027008-3: as R77 on sheet PROC074B_LP_Connector
R162 = CMP-0027008-3: as R76 on sheet PROC074B_LP_Connector
R163-R166 R169 = CMP-0026071-2: RES, 1.00 k, 1%, 0.063 W, 0402; Manufacturer: Vishay-Dale; Power_W: 63mW; TempCo: 100 ppm/C; Value_Code: 1k00; U/M: EA; Value: 1.00k; EIA_Code: E96; Res_ohm: 1k; SizeX_mm: 1; SizeY_mm: 0.5; SizeZ_mm: 0.6; Value2: 0.063W; VDC_V: 50V; AEC Category: Q200
R167 = CMP-0026404-1: RES, 49.9, 1%, 0.063 W, 0402; Manufacturer: Vishay-Dale; Power_W: 63mW; TempCo: 100 ppm/C; Value_Code: 49R9; U/M: EA; Value: 49.9; EIA_Code: E96; SizeX_mm: 1; SizeY_mm: 0.5; SizeZ_mm: 0.6; Value2: 0.063W; VDC_V: 50V; AEC Category: Q200
R168 = CMP-0025958-2: as R37 on sheet PROC074B_HD_Conn_JTAG_HDR
R170 = CMP-0026413-1: RES, 4.87 k, 1%, 0.063 W, 0402; Manufacturer: Vishay-Dale; Power_W: 63mW; TempCo: 100 ppm/C; Value_Code: 4k87; U/M: EA; Value: 4.87k; EIA_Code: E96; SizeX_mm: 1; SizeY_mm: 0.5; SizeZ_mm: 0.6; Value2: 0.063W; VDC_V: 50V; AEC Category: Q200
U8 = CMP-0029856-2: Tiva C Series Microcontroller, 1024 KB Flash, 256 KB SRAM, 12 Bit, 20 Channels, -40 to 105 degC, 128-Pin TQFP (PDT), Green (RoHS & no Sb/Br), Tray; Manufacturer: Texas Instruments; ADC Channels: 20; CPU: ARM Cortex-M4; Flash: 1024 KB; ADC Resolution: 12 Bits; Max Speed: 120 MHz; SRAM: 256 KB; SizeAreaWB_mm2: 324.0; SizeArea_mm2: 256.0; SizeX_mm: 16.0; SizeZ_mm: 1.2; CompType: IC
U9 = CMP-0033001-1: Precision Micropower Shunt Voltage Reference, 0.5% accuracy, 2.5 V, 15 ppm / degC, 15 mA, -40 to 125 degC, 3-pin SOT-23 (DBZ), Green (RoHS & no Sb/Br); Manufacturer: Texas Instruments; Initial Accuracy @ 25/deg C(%): 0.5; Temp Coeff(Typ)(ppm/ degree C): 15; Temp Coeff(Max)(ppm/ degree C): 100; Rating: Catalog; Min Iz for Regulation(uA): 75; VO(V): 2.5
Y1 = CMP-0078214-2: Crystal, 16 MHz, 15 ppm, 8 pF, AEC-Q200 Grade 1, SMD; Manufacturer: NDK; TaMin_C: -40°C; Frequency Tolerance: 10 ppm; Frequency Stability: 150 ppm; Load Capacitance: 7.36 pF; Frequency_Fixed: 16MHz; TaMax_C: 125°C; AEC Qualified: N; AEC Grade: 1; AEC Category: Q200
